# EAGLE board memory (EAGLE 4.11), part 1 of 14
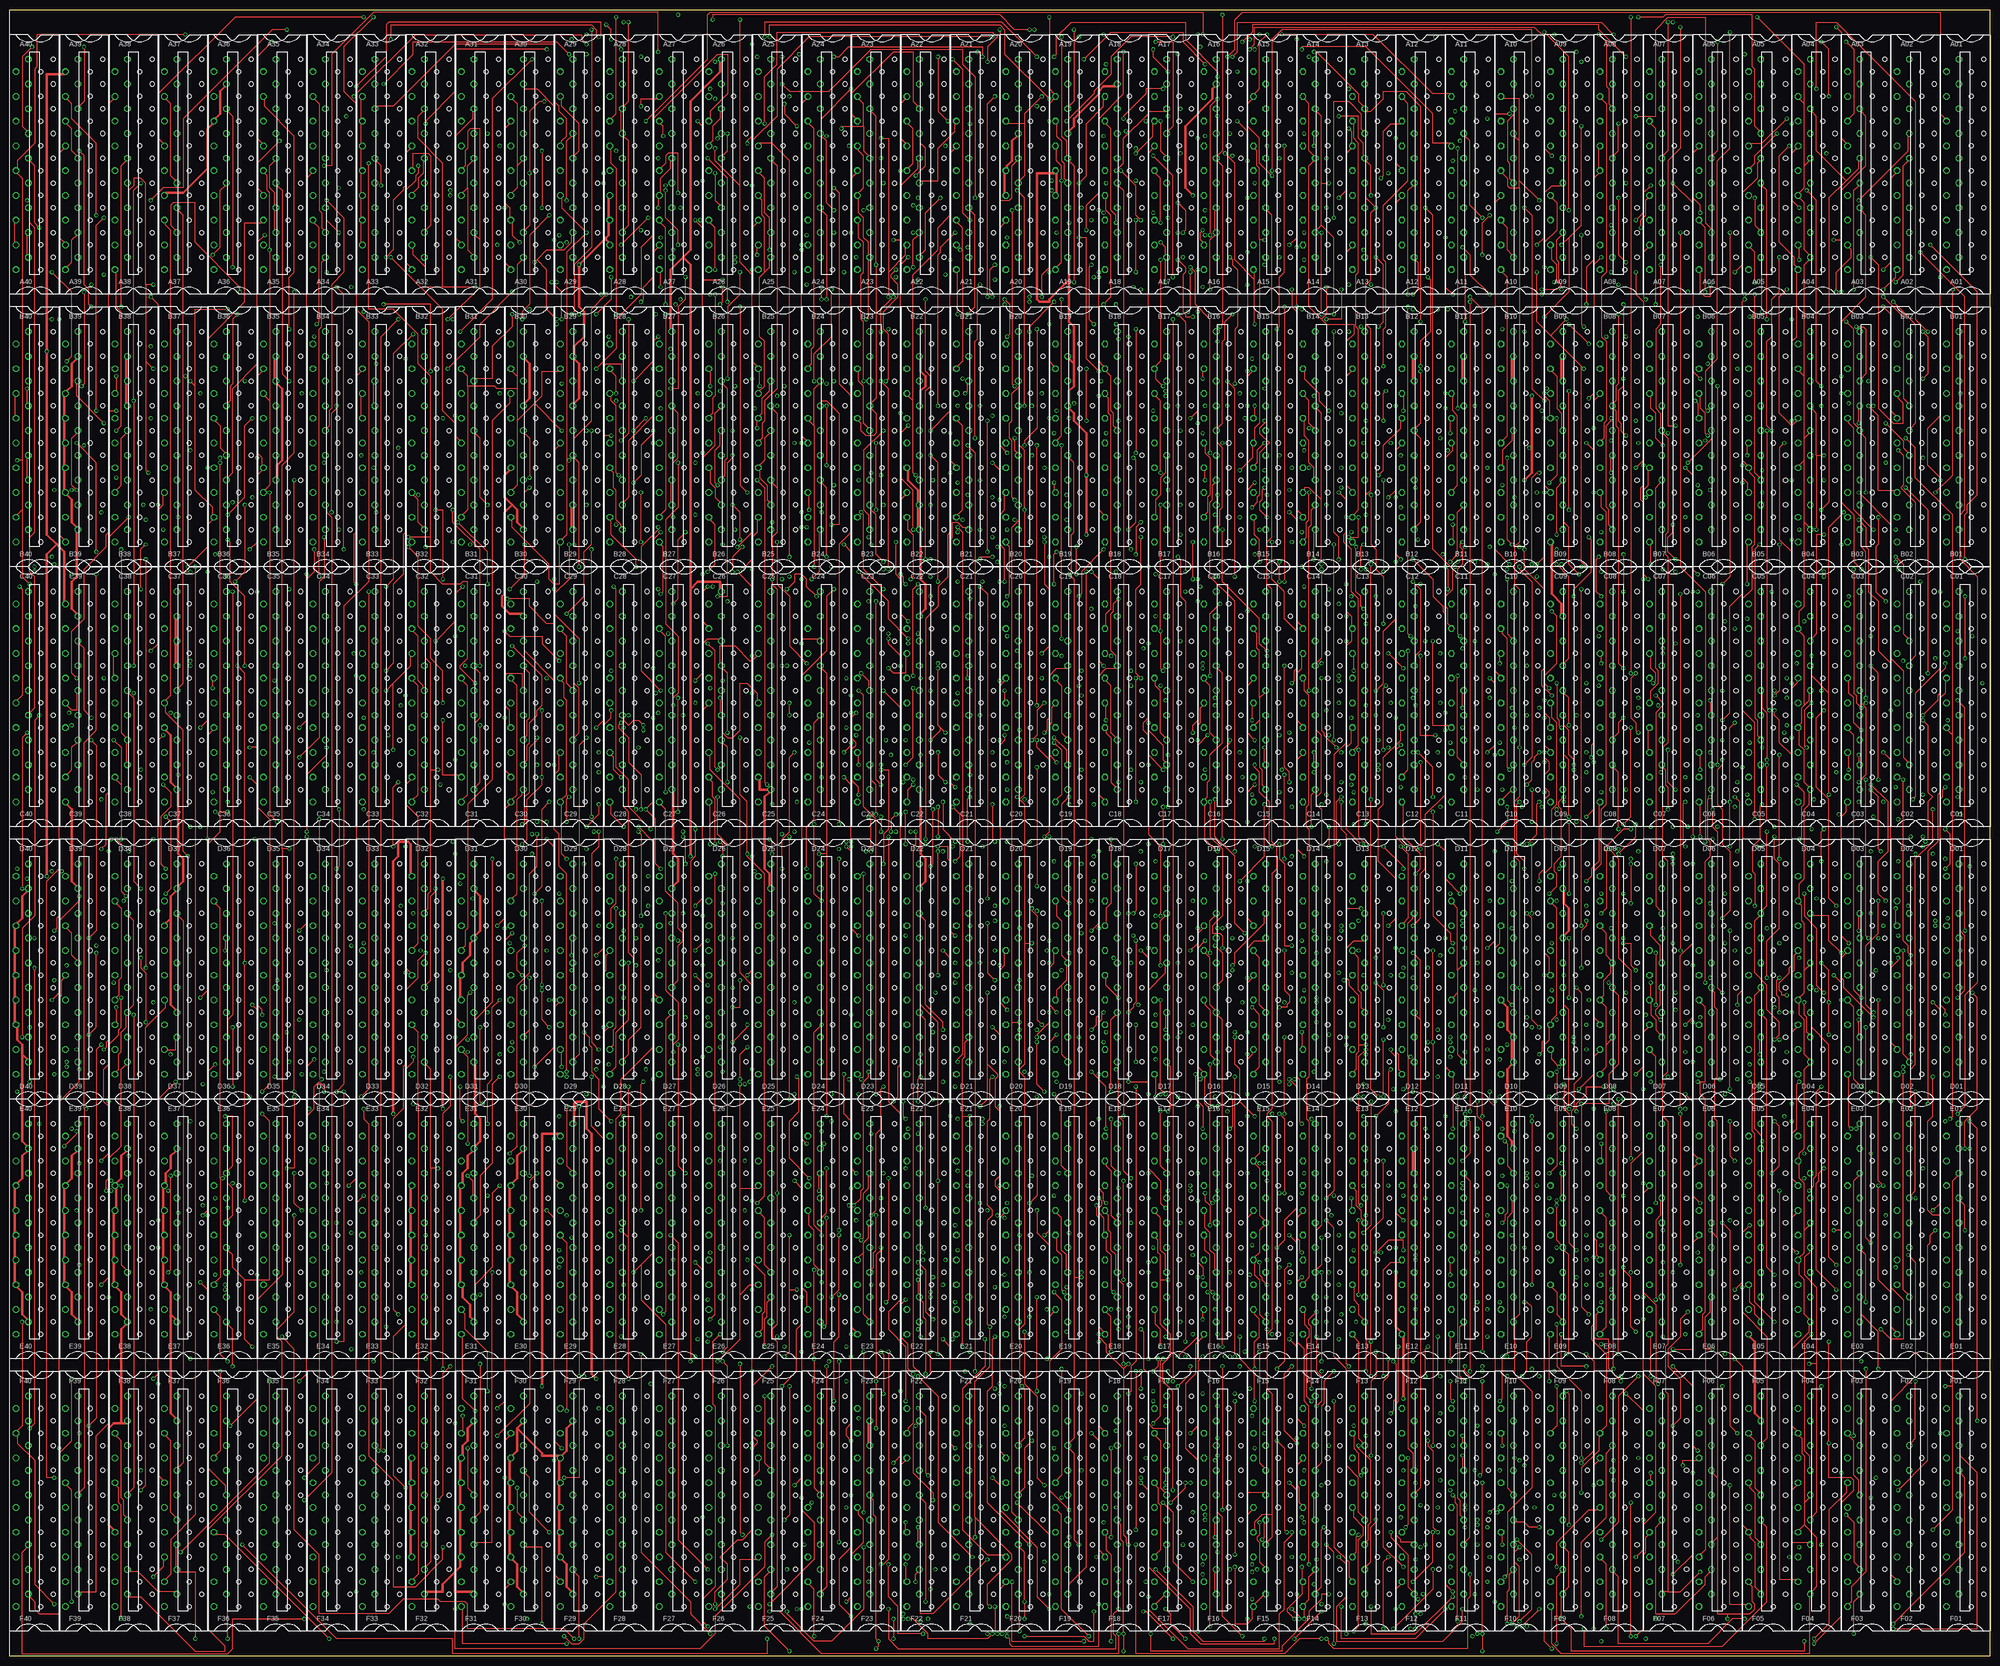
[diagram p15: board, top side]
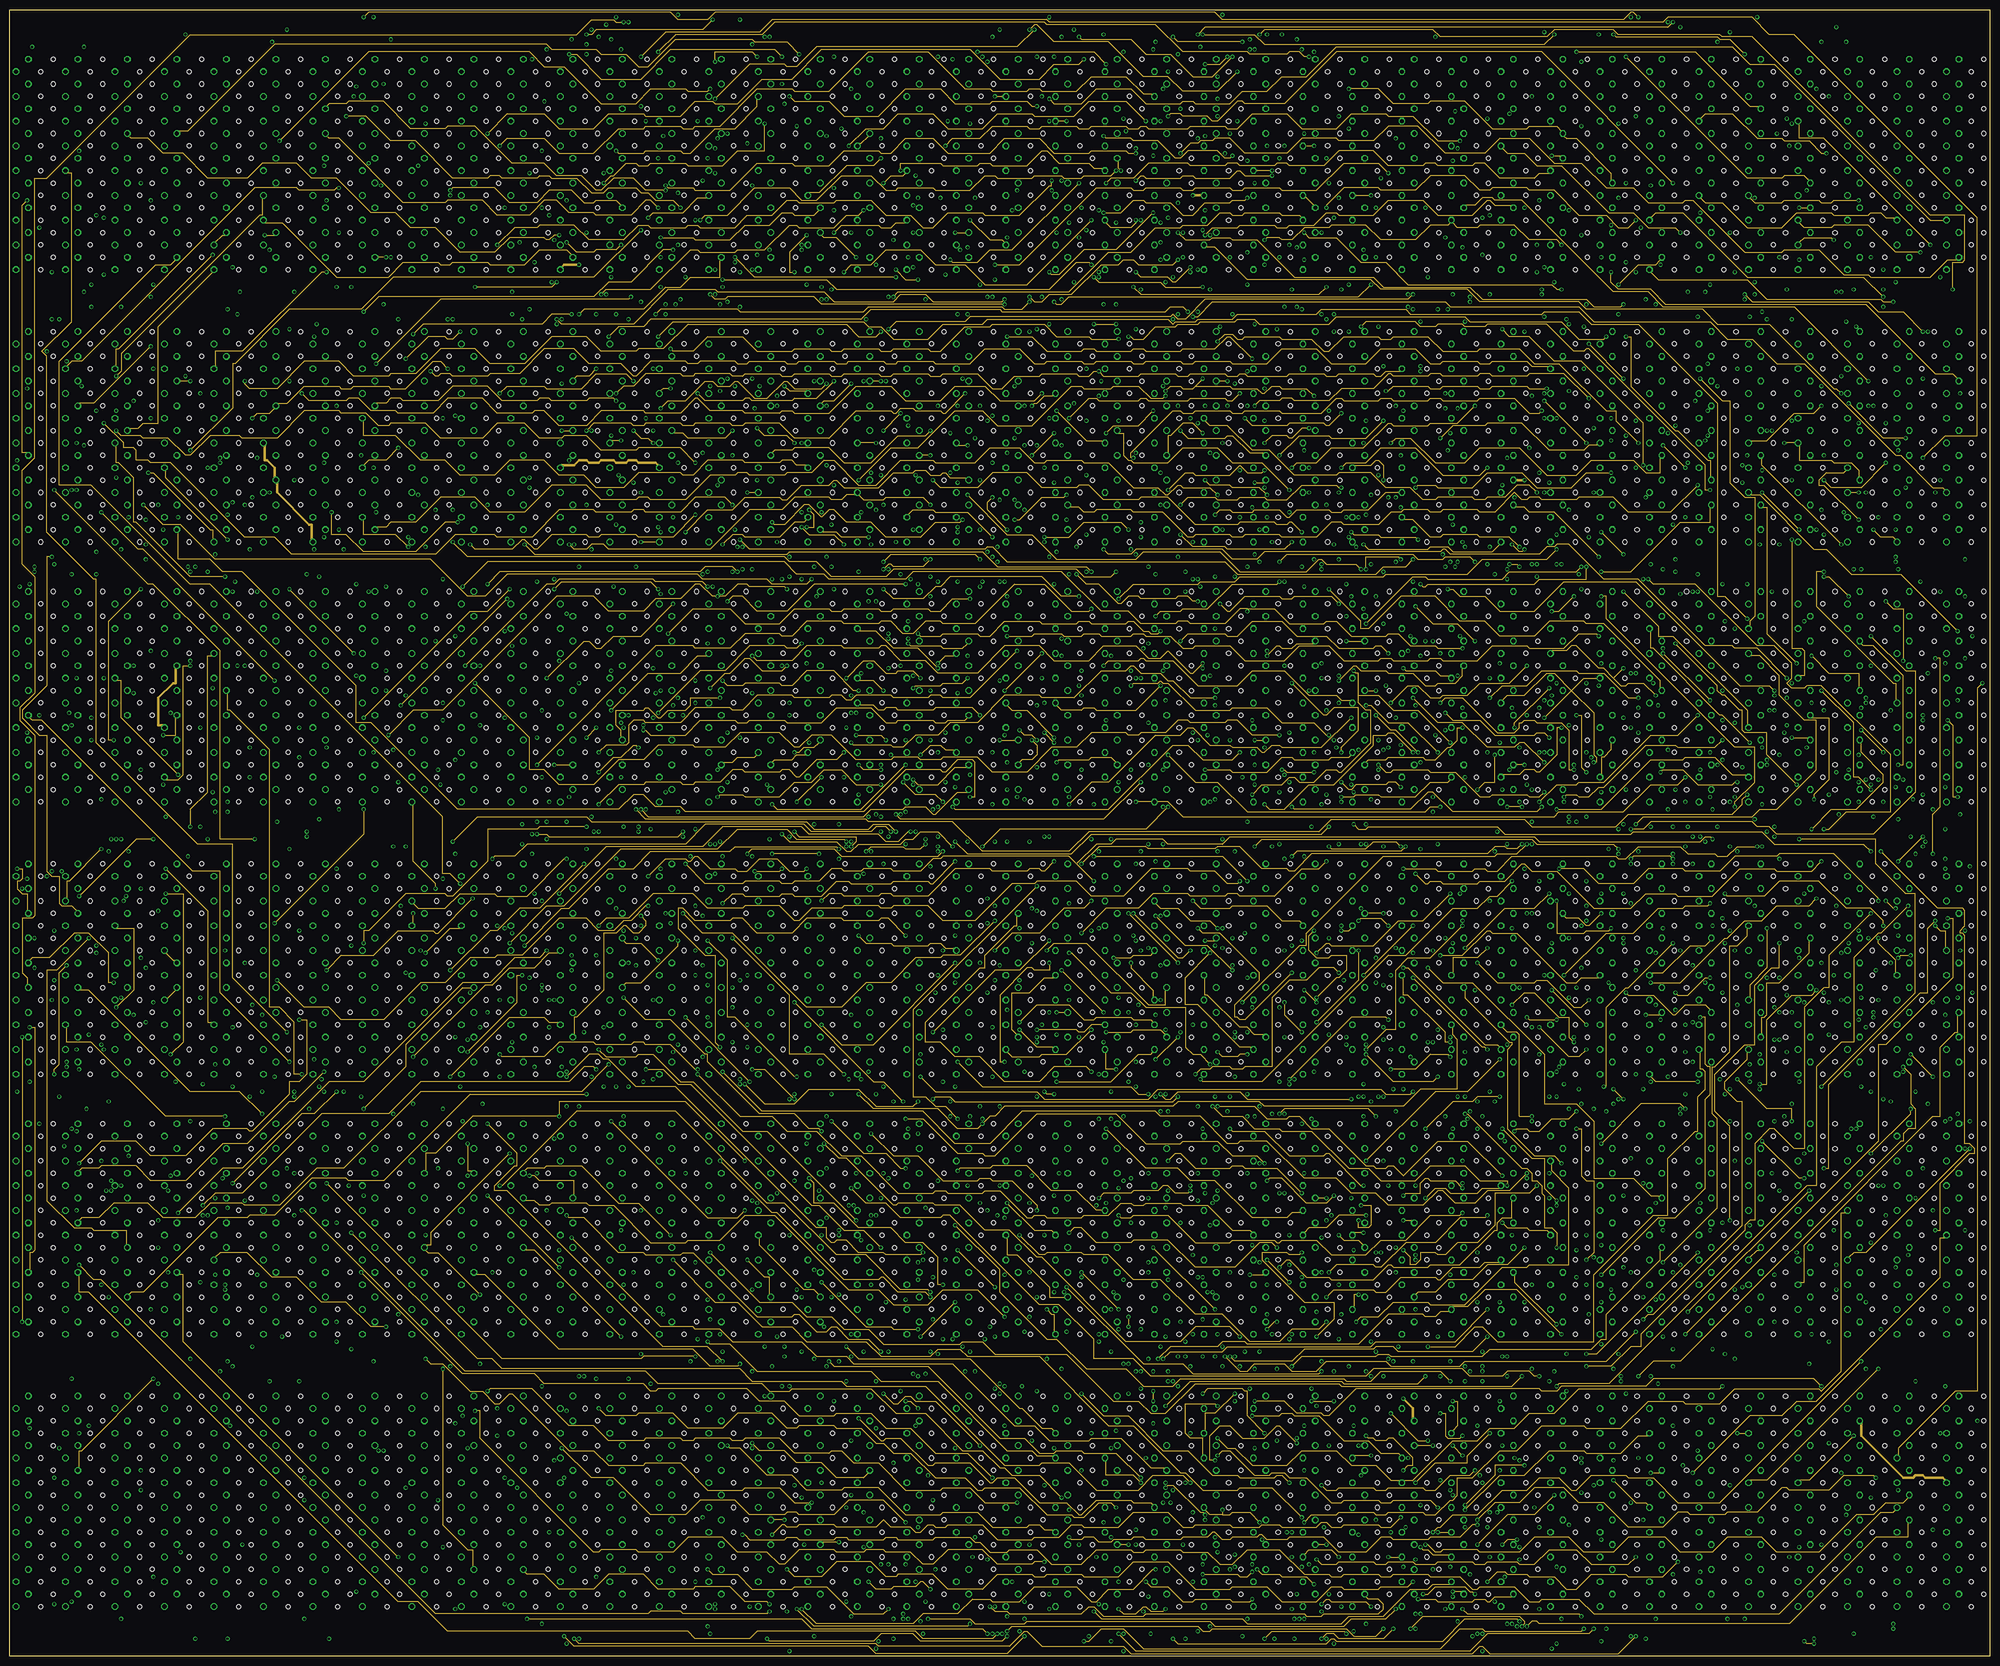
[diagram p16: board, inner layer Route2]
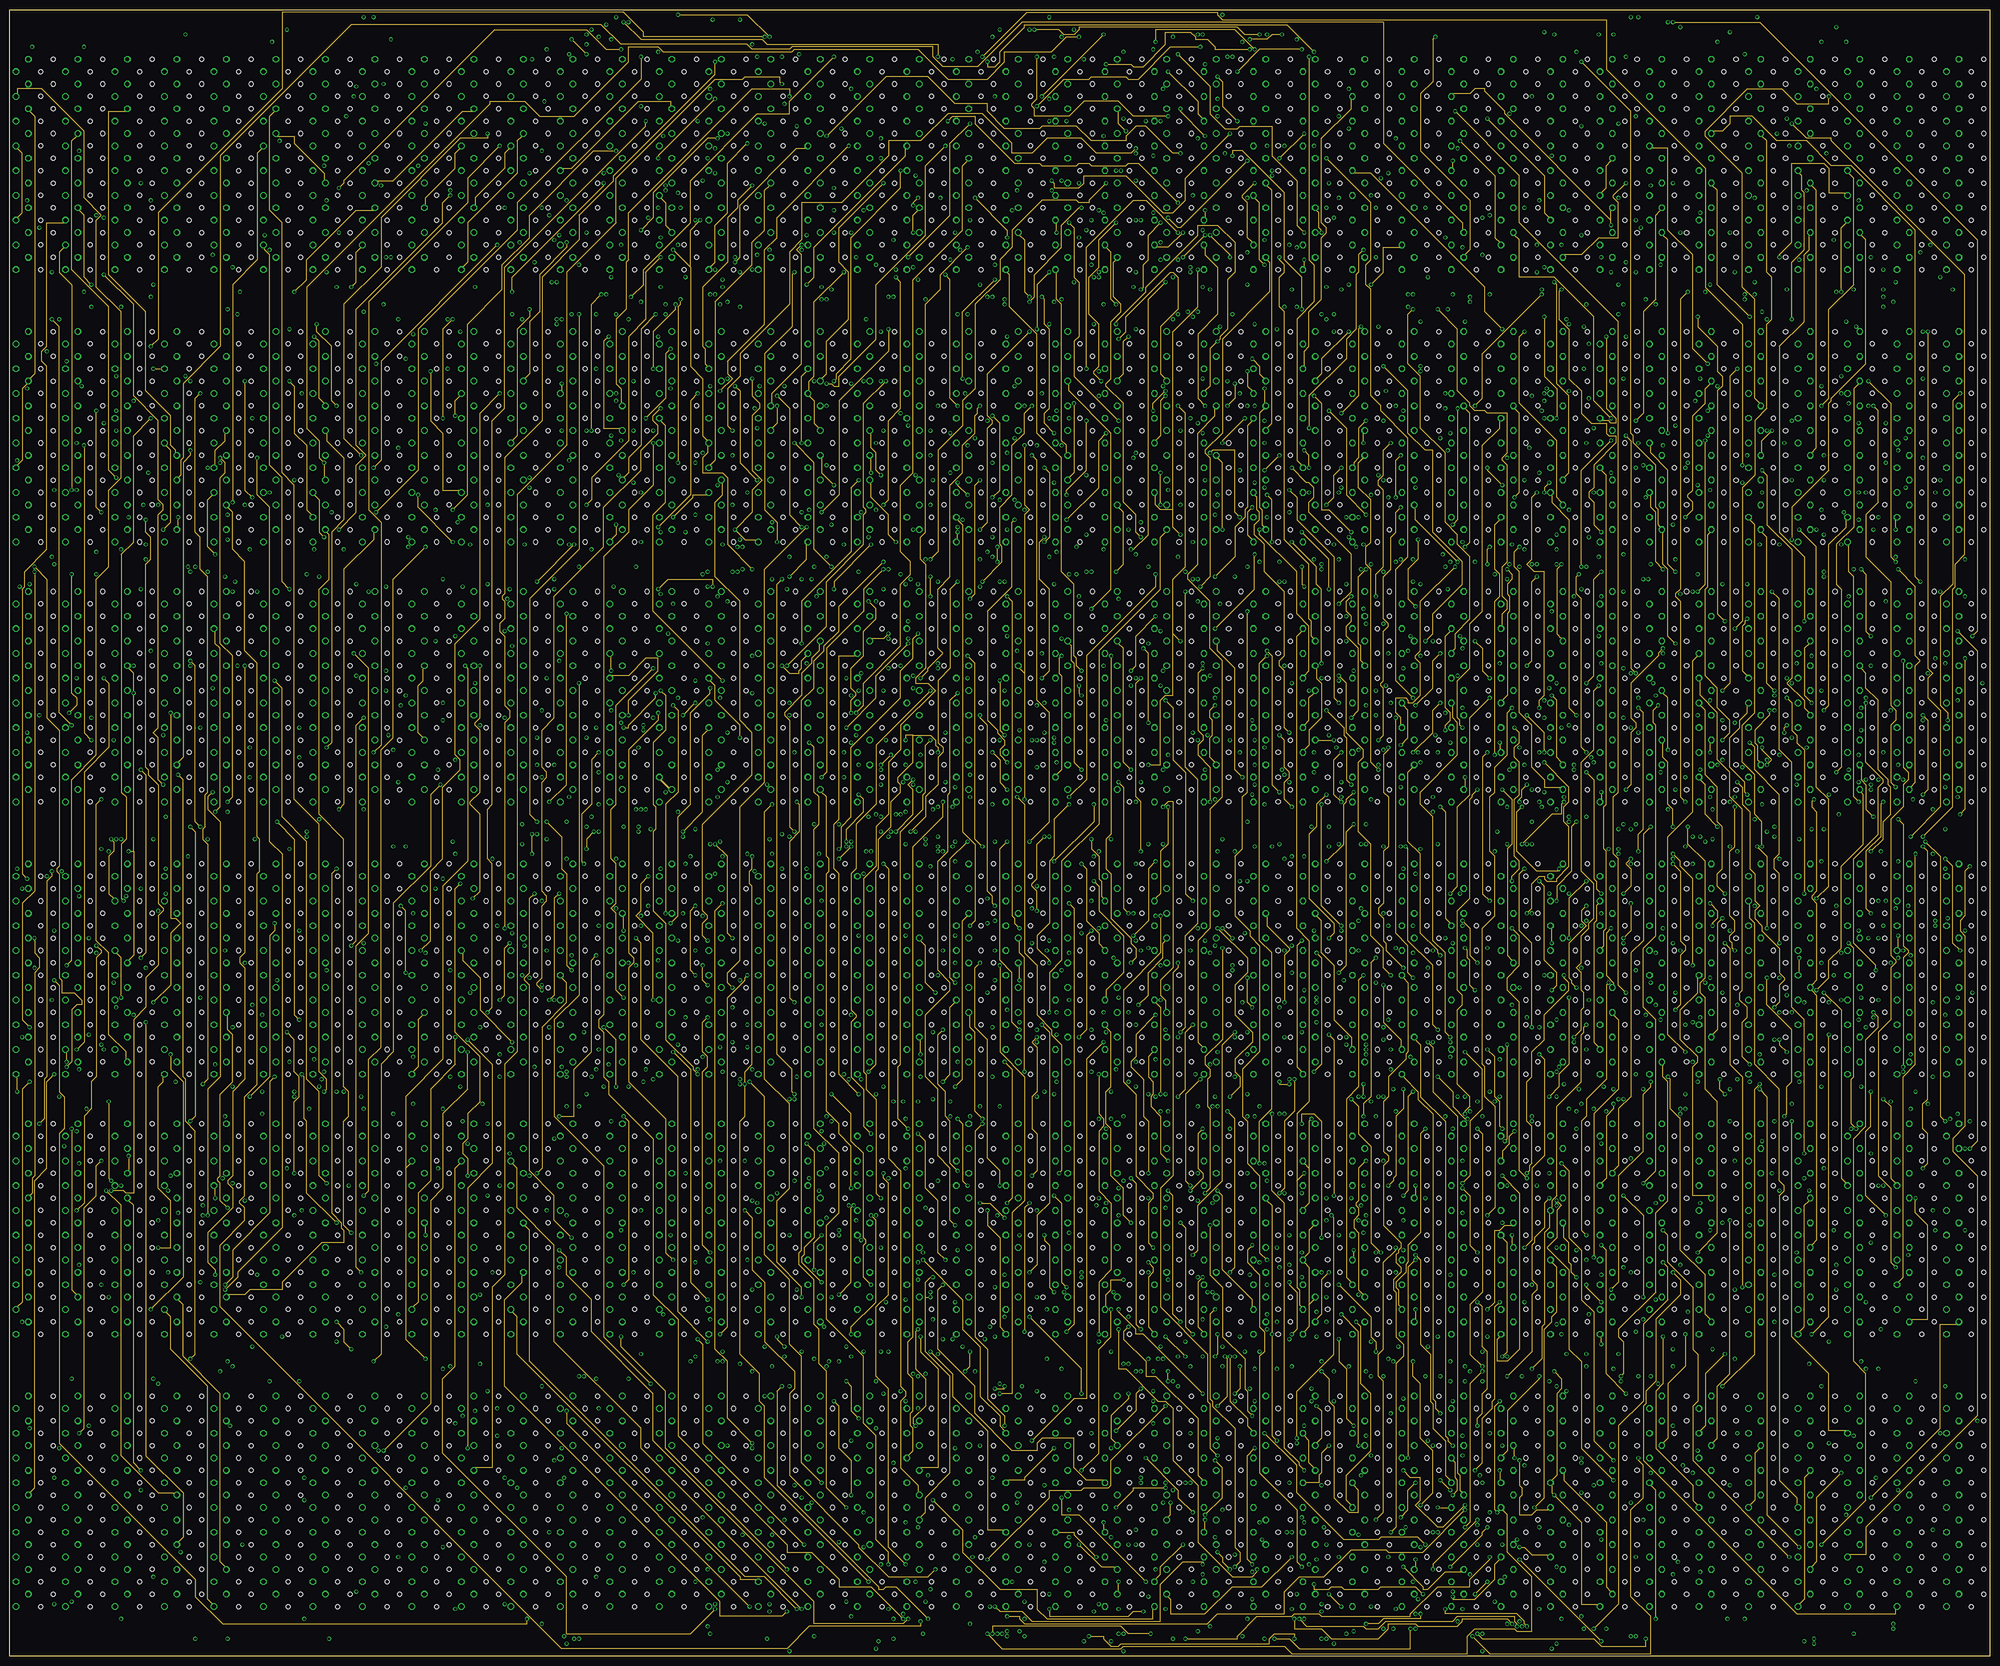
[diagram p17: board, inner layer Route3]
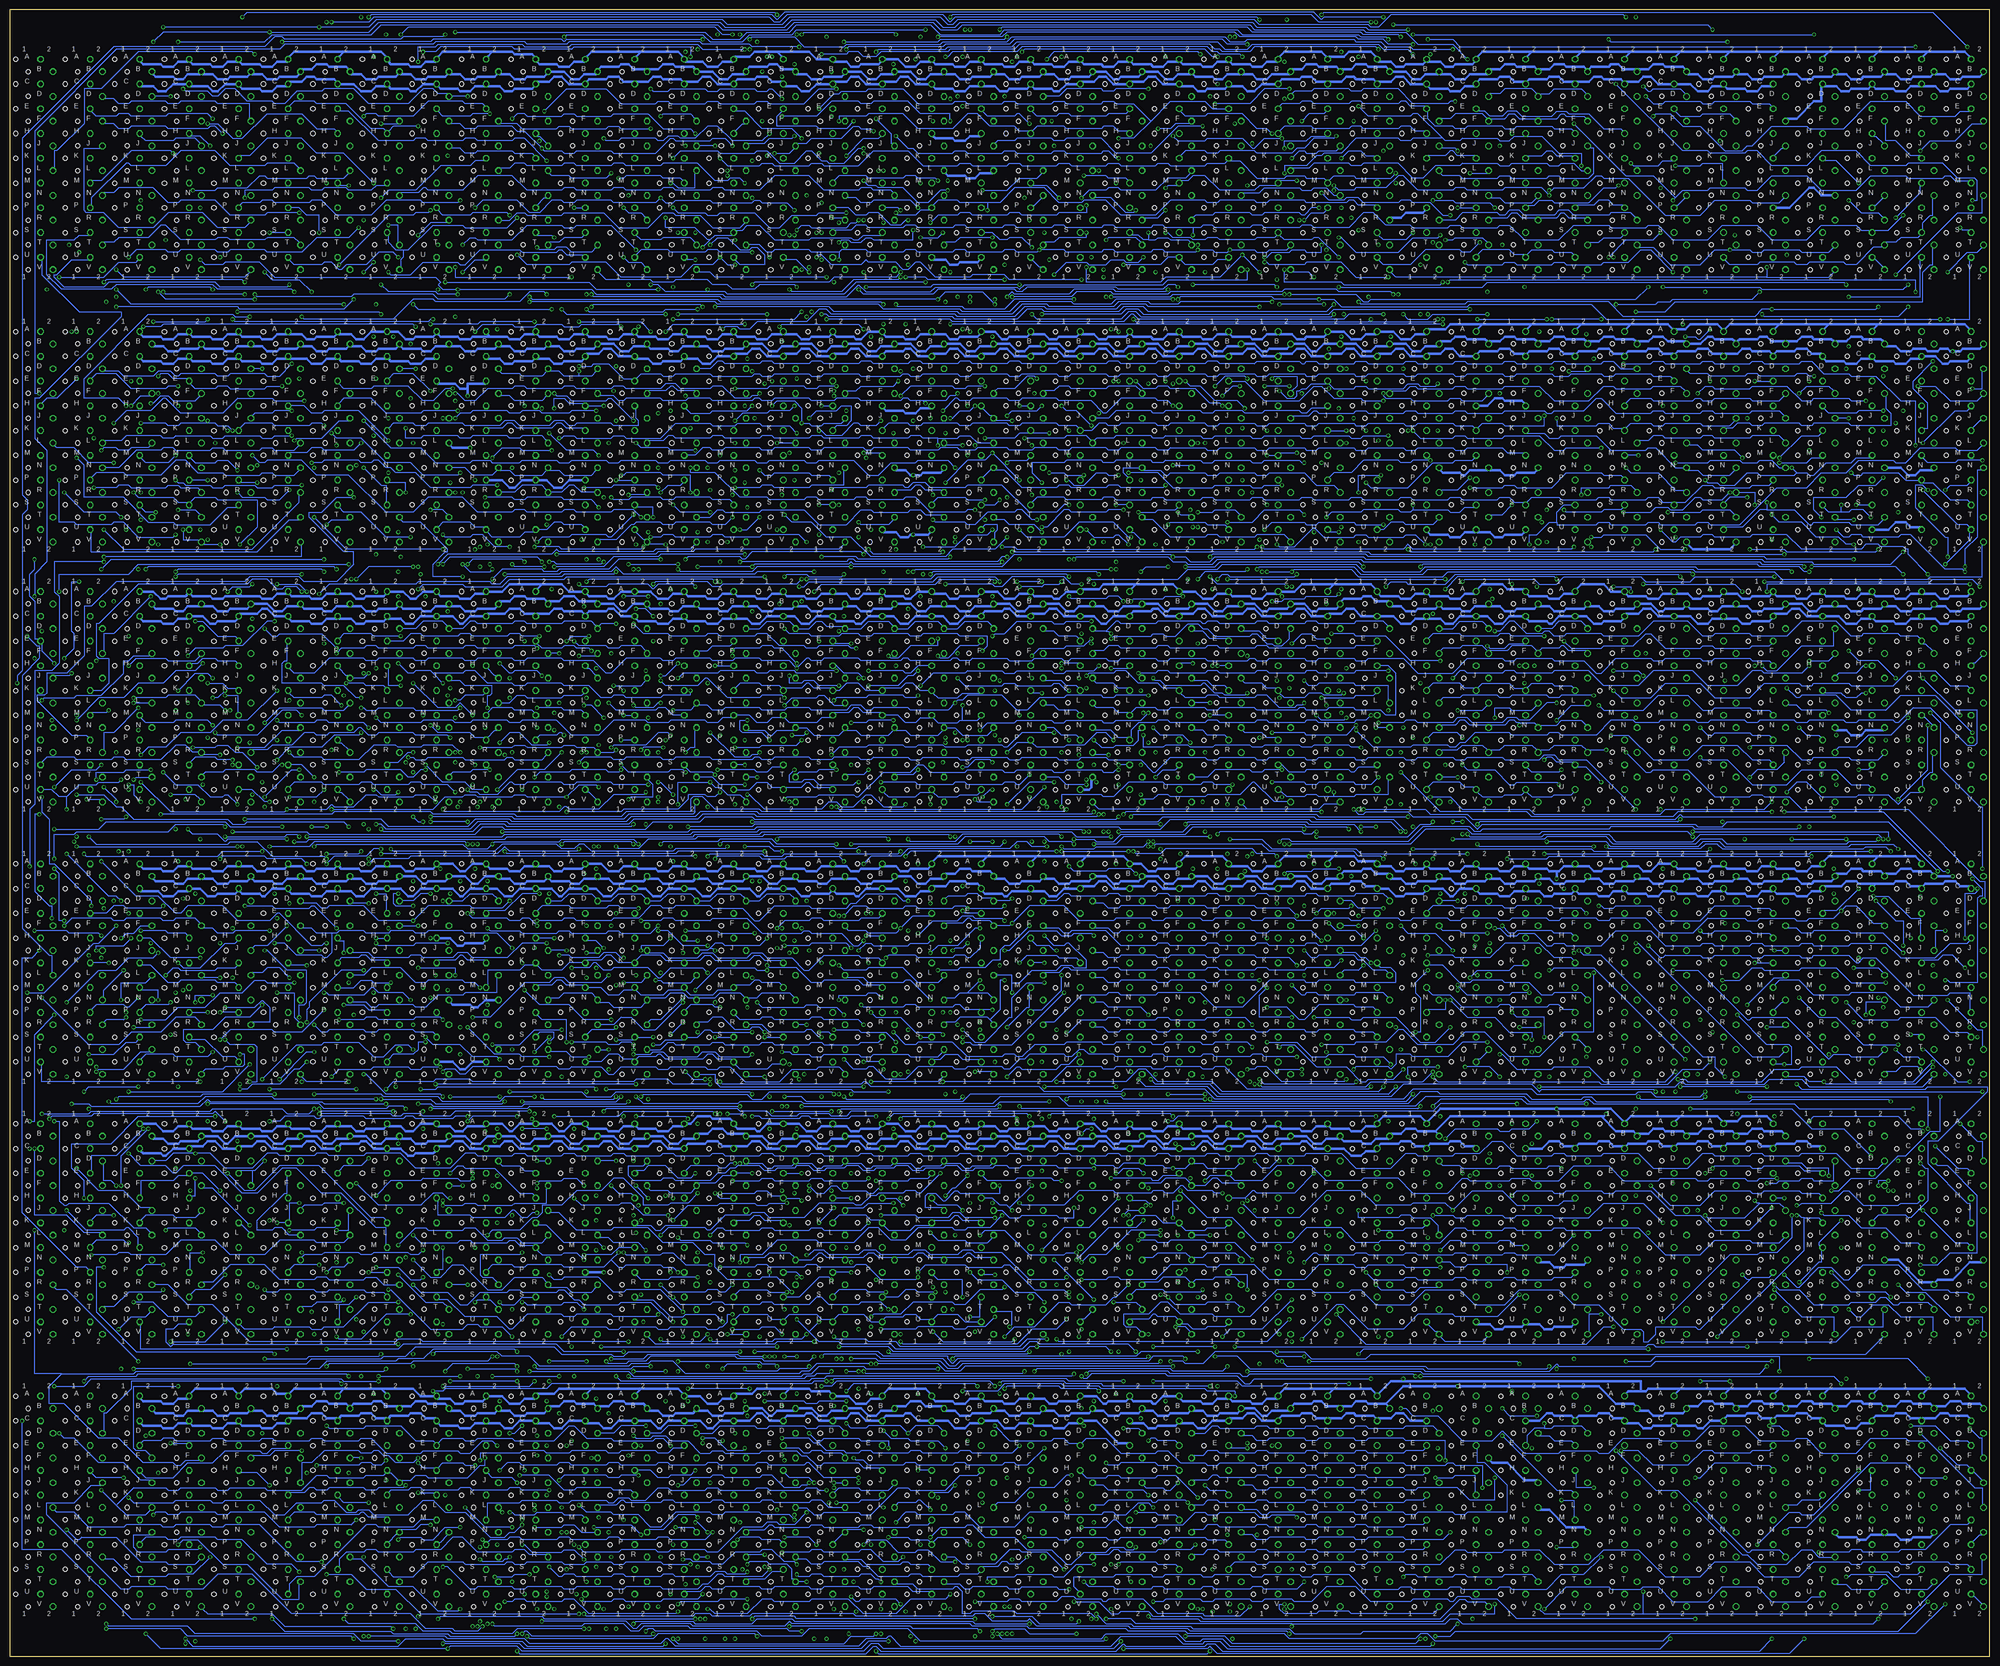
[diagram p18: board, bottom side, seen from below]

Size 508 x 422.28 mm. Coordinates in mm from the lower left corner, seen from the top.
Outline: 0,6.35 0,422.28 508,422.28 508,0 0,0 0,6.35
Copper layers (1*2*3*16): Top 0.035mm / dielectric 1.5mm / Route2 0.035mm / dielectric 0.15mm / Route3 0.035mm / dielectric 0.2mm / Bottom 0.035mm
Design rules "default": minimum track width 10mil, minimum drill 24mil, track to track 8mil, track to pad 8mil, pad to pad 8mil, via to via 8mil, smd to smd 8mil, copper to edge 10mil, drill to drill 8mil, minimum pad ring 10mil, minimum via ring 8mil, stop-mask expansion 4mil, vias tented up to drill 0mil, thermal gap 10mil
Net classes: 1 Supply: width 0.635 mm

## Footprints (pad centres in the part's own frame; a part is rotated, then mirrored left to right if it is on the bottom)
H807S = drill 1.092 octagon: A2 -1.587,28.575; B2 -4.763,25.4; C2 -1.587,22.225; D2 -4.763,19.05; E2 -1.587,15.875; F2 -4.763,12.7; H2 -1.587,9.525; J2 -4.763,6.35; K2 -1.587,3.175; L2 -4.763,0; M2 -1.587,-3.175; N2 -4.763,-6.35; P2 -1.587,-9.525; R2 -4.763,-12.7; S2 -1.587,-15.875; T2 -4.763,-19.05; U2 -1.587,-22.225; V2 -4.763,-25.4 | hole 1.092: 4.763,28.575; 1.587,25.4; 4.763,22.225; 1.587,19.05; 4.763,15.875; 1.587,12.7; 4.763,9.525; 1.587,6.35; 4.763,3.175; 1.587,0; 4.763,-3.175; 1.587,-6.35; 4.763,-9.525; 1.587,-12.7; 4.763,-15.875; 1.587,-19.05; 4.763,-22.225; 1.587,-25.4

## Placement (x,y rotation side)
A01  W023S  [H807S]  501.65,381 0 top
A02  W023S  [H807S]  488.95,381 0 top
A03  R001S  [H807S]  476.25,381 0 top
A04  R202S  [H807S]  463.55,381 0 top
A05  W050S  [H807S]  450.85,381 0 top
A06  W050S  [H807S]  438.15,381 0 top
A07  W050S  [H807S]  425.45,381 0 top
A08  R113S  [H807S]  412.75,381 0 top
A09  R107S  [H807S]  400.05,381 0 top
A10  R113S  [H807S]  387.35,381 0 top
A11  R111S  [H807S]  374.65,381 0 top
A12  R002S  [H807S]  361.95,381 0 top
A13  R002S  [H807S]  349.25,381 0 top
A14  R111S  [H807S]  336.55,381 0 top
A15  R113S  [H807S]  323.85,381 0 top
A16  R602S  [H807S]  311.15,381 0 top
A17  R107S  [H807S]  298.45,381 0 top
A18  R107S  [H807S]  285.75,381 0 top
A19  R603S  [H807S]  273.05,381 0 top
A20  R603S  [H807S]  260.35,381 0 top
A21  R111S  [H807S]  247.65,381 0 top
A22  R001S  [H807S]  234.95,381 0 top
A23  R111S  [H807S]  222.25,381 0 top
A24  R107S  [H807S]  209.55,381 0 top
A25  R111S  [H807S]  196.85,381 0 top
A26  R113S  [H807S]  184.15,381 0 top
A27  R113S  [H807S]  171.45,381 0 top
A28  R602S  [H807S]  158.75,381 0 top
A29  R202S  [H807S]  146.05,381 0 top
A30  R202S  [H807S]  133.35,381 0 top
A31  R202S  [H807S]  120.65,381 0 top
A32  R202S  [H807S]  107.95,381 0 top
A33  R001S  [H807S]  95.25,381 0 top
A34  R111S  [H807S]  82.55,381 0 top
A35  R001S  [H807S]  69.85,381 0 top
A36  R302S  [H807S]  57.15,381 0 top
A37  R602S  [H807S]  44.45,381 0 top
A38  R111S  [H807S]  31.75,381 0 top
A39  R002S  [H807S]  19.05,381 0 top
A40  R107S  [H807S]  6.35,381 0 top
B01  W023S  [H807S]  501.65,311.15 0 top
B02  W023S  [H807S]  488.95,311.15 0 top
B03  W050S  [H807S]  476.25,311.15 0 top
B04  R202S  [H807S]  463.55,311.15 0 top
B05  W005S  [H807S]  450.85,311.15 0 top
B06  W050S  [H807S]  438.15,311.15 0 top
B07  W050S  [H807S]  425.45,311.15 0 top
B08  R107S  [H807S]  412.75,311.15 0 top
B09  R202S  [H807S]  400.05,311.15 0 top
B10  R202S  [H807S]  387.35,311.15 0 top
B11  R202S  [H807S]  374.65,311.15 0 top
B12  R202S  [H807S]  361.95,311.15 0 top
B13  R111S  [H807S]  349.25,311.15 0 top
B14  R002S  [H807S]  336.55,311.15 0 top
B15  R113S  [H807S]  323.85,311.15 0 top
B16  R107S  [H807S]  311.15,311.15 0 top
B17  R113S  [H807S]  298.45,311.15 0 top
B18  R603S  [H807S]  285.75,311.15 0 top
B19  R603S  [H807S]  273.05,311.15 0 top
B20  R111S  [H807S]  260.35,311.15 0 top
B21  R002S  [H807S]  247.65,311.15 0 top
B22  R603S  [H807S]  234.95,311.15 0 top
B23  R111S  [H807S]  222.25,311.15 0 top
B24  R113S  [H807S]  209.55,311.15 0 top
B25  R113S  [H807S]  196.85,311.15 0 top
B26  R002S  [H807S]  184.15,311.15 0 top
B27  R602S  [H807S]  171.45,311.15 0 top
B28  R202S  [H807S]  158.75,311.15 0 top
B29  R603S  [H807S]  146.05,311.15 0 top
B30  R603S  [H807S]  133.35,311.15 0 top
B31  R603S  [H807S]  120.65,311.15 0 top
B32  R401S  [H807S]  107.95,311.15 0 top
B33  R107S  [H807S]  95.25,311.15 0 top
B34  R202S  [H807S]  82.55,311.15 0 top
B35  R202S  [H807S]  69.85,311.15 0 top
B36  R113S  [H807S]  57.15,311.15 0 top
B37  R107S  [H807S]  44.45,311.15 0 top
B38  R603S  [H807S]  31.75,311.15 0 top
B39  W028S  [H807S]  19.05,311.15 0 top
B40  W005S  [H807S]  6.35,311.15 0 top
C01  W023S  [H807S]  501.65,244.47 0 top
C02  W023S  [H807S]  488.95,244.47 0 top
C03  W050S  [H807S]  476.25,244.47 0 top
C04  R202S  [H807S]  463.55,244.47 0 top
C05  R107S  [H807S]  450.85,244.47 0 top
C06  W050S  [H807S]  438.15,244.47 0 top
C07  R111S  [H807S]  425.45,244.47 0 top
C08  R002S  [H807S]  412.75,244.47 0 top
C09  R107S  [H807S]  400.05,244.47 0 top
C10  R111S  [H807S]  387.35,244.47 0 top
C11  R001S  [H807S]  374.65,244.47 0 top
C12  R111S  [H807S]  361.95,244.47 0 top
C13  R107S  [H807S]  349.25,244.47 0 top
C14  R113S  [H807S]  336.55,244.47 0 top
C15  R202S  [H807S]  323.85,244.47 0 top
C16  R202S  [H807S]  311.15,244.47 0 top
C17  R202S  [H807S]  298.45,244.47 0 top
C18  R202S  [H807S]  285.75,244.47 0 top
C19  R202S  [H807S]  273.05,244.47 0 top
C20  R202S  [H807S]  260.35,244.47 0 top
C21  R107S  [H807S]  247.65,244.47 0 top
C22  M517S  [H807S]  234.95,244.47 0 top
C23  W512S  [H807S]  222.25,244.47 0 top
C24  R107S  [H807S]  209.55,244.47 0 top
C25  M517S  [H807S]  196.85,244.47 0 top
C26  W512S  [H807S]  184.15,244.47 0 top
C27  M517S  [H807S]  171.45,244.47 0 top
C28  W023S  [H807S]  158.75,244.47 0 top
C29  R202S  [H807S]  146.05,244.47 0 top
C30  R202S  [H807S]  133.35,244.47 0 top
C31  R202S  [H807S]  120.65,244.47 0 top
C32  R202S  [H807S]  107.95,244.47 0 top
C33  EMPTYS  [H807S]  95.25,244.47 0 top
C34  EMPTYS  [H807S]  82.55,244.47 0 top
C35  EMPTYS  [H807S]  69.85,244.47 0 top
C36  R107S  [H807S]  57.15,244.47 0 top
C37  R603S  [H807S]  44.45,244.47 0 top
C38  R602S  [H807S]  31.75,244.47 0 top
C39  W501S  [H807S]  19.05,244.47 0 top
C40  W506S  [H807S]  6.35,244.47 0 top
D01  W023S  [H807S]  501.65,174.62 0 top
D02  W023S  [H807S]  488.95,174.62 0 top
D03  W050S  [H807S]  476.25,174.62 0 top
D04  R202S  [H807S]  463.55,174.62 0 top
D05  R107S  [H807S]  450.85,174.62 0 top
D06  R113S  [H807S]  438.15,174.62 0 top
D07  R113S  [H807S]  425.45,174.62 0 top
D08  R113S  [H807S]  412.75,174.62 0 top
D09  R603S  [H807S]  400.05,174.62 0 top
D10  R603S  [H807S]  387.35,174.62 0 top
D11  R202S  [H807S]  374.65,174.62 0 top
D12  R202S  [H807S]  361.95,174.62 0 top
D13  R202S  [H807S]  349.25,174.62 0 top
D14  R202S  [H807S]  336.55,174.62 0 top
D15  R202S  [H807S]  323.85,174.62 0 top
D16  R202S  [H807S]  311.15,174.62 0 top
D17  R151S  [H807S]  298.45,174.62 0 top
D18  R107S  [H807S]  285.75,174.62 0 top
D19  R202S  [H807S]  273.05,174.62 0 top
D20  R202S  [H807S]  260.35,174.62 0 top
D21  M507S  [H807S]  247.65,174.62 0 top
D22  M507S  [H807S]  234.95,174.62 0 top
D23  EMPTYS  [H807S]  222.25,174.62 0 top
D24  EMPTYS  [H807S]  209.55,174.62 0 top
D25  EMPTYS  [H807S]  196.85,174.62 0 top
D26  EMPTYS  [H807S]  184.15,174.62 0 top
D27  M507S  [H807S]  171.45,174.62 0 top
D28  W023S  [H807S]  158.75,174.62 0 top
D29  R107S  [H807S]  146.05,174.62 0 top
D30  R401S  [H807S]  133.35,174.62 0 top
D31  R603S  [H807S]  120.65,174.62 0 top
D32  R113S  [H807S]  107.95,174.62 0 top
D33  EMPTYS  [H807S]  95.25,174.62 0 top
D34  EMPTYS  [H807S]  82.55,174.62 0 top
D35  EMPTYS  [H807S]  69.85,174.62 0 top
D36  R111S  [H807S]  57.15,174.62 0 top
D37  R302S  [H807S]  44.45,174.62 0 top
D38  R202S  [H807S]  31.75,174.62 0 top
D39  R002S  [H807S]  19.05,174.62 0 top
D40  W028S  [H807S]  6.35,174.62 0 top
E01  W023S  [H807S]  501.65,107.95 0 top
E02  W023S  [H807S]  488.95,107.95 0 top
E03  R001S  [H807S]  476.25,107.95 0 top
E04  R202S  [H807S]  463.55,107.95 0 top
E05  W501S  [H807S]  450.85,107.95 0 top
E06  R202S  [H807S]  438.15,107.95 0 top
E07  W050S  [H807S]  425.45,107.95 0 top
E08  W005S  [H807S]  412.75,107.95 0 top
E09  R113S  [H807S]  400.05,107.95 0 top
E10  R113S  [H807S]  387.35,107.95 0 top
E11  R113S  [H807S]  374.65,107.95 0 top
E12  R202S  [H807S]  361.95,107.95 0 top
E13  R113S  [H807S]  349.25,107.95 0 top
E14  R113S  [H807S]  336.55,107.95 0 top
E15  R202S  [H807S]  323.85,107.95 0 top
E16  R202S  [H807S]  311.15,107.95 0 top
E17  R202S  [H807S]  298.45,107.95 0 top
E18  R202S  [H807S]  285.75,107.95 0 top
E19  R202S  [H807S]  273.05,107.95 0 top
E20  R202S  [H807S]  260.35,107.95 0 top
E21  EMPTYS  [H807S]  247.65,107.95 0 top
E22  R401S  [H807S]  234.95,107.95 0 top
E23  R202S  [H807S]  222.25,107.95 0 top
E24  R202S  [H807S]  209.55,107.95 0 top
E25  R202S  [H807S]  196.85,107.95 0 top
E26  EMPTYS  [H807S]  184.15,107.95 0 top
E27  EMPTYS  [H807S]  171.45,107.95 0 top
E28  EMPTYS  [H807S]  158.75,107.95 0 top
E29  R111S  [H807S]  146.05,107.95 0 top
E30  W021S  [H807S]  133.35,107.95 0 top
E31  W021S  [H807S]  120.65,107.95 0 top
E32  W021S  [H807S]  107.95,107.95 0 top
E33  EMPTYS  [H807S]  95.25,107.95 0 top
E34  EMPTYS  [H807S]  82.55,107.95 0 top
E35  EMPTYS  [H807S]  69.85,107.95 0 top
E36  R113S  [H807S]  57.15,107.95 0 top
E37  W028S  [H807S]  44.45,107.95 0 top
E38  W028S  [H807S]  31.75,107.95 0 top
E39  W028S  [H807S]  19.05,107.95 0 top
E40  W028S  [H807S]  6.35,107.95 0 top
F01  W023S  [H807S]  501.65,38.1 0 top
F02  W023S  [H807S]  488.95,38.1 0 top
F03  R202S  [H807S]  476.25,38.1 0 top
F04  R202S  [H807S]  463.55,38.1 0 top
F05  R202S  [H807S]  450.85,38.1 0 top
F06  R001S  [H807S]  438.15,38.1 0 top
F07  R111S  [H807S]  425.45,38.1 0 top
F08  R111S  [H807S]  412.75,38.1 0 top
F09  R111S  [H807S]  400.05,38.1 0 top
F10  R107S  [H807S]  387.35,38.1 0 top
F11  R107S  [H807S]  374.65,38.1 0 top
F12  R107S  [H807S]  361.95,38.1 0 top
F13  R107S  [H807S]  349.25,38.1 0 top
F14  R113S  [H807S]  336.55,38.1 0 top
F15  R111S  [H807S]  323.85,38.1 0 top
F16  R001S  [H807S]  311.15,38.1 0 top
F17  R111S  [H807S]  298.45,38.1 0 top
F18  R107S  [H807S]  285.75,38.1 0 top
F19  R107S  [H807S]  273.05,38.1 0 top
F20  R107S  [H807S]  260.35,38.1 0 top
F21  EMPTYS  [H807S]  247.65,38.1 0 top
F22  W005S  [H807S]  234.95,38.1 0 top
F23  R202S  [H807S]  222.25,38.1 0 top
F24  R107S  [H807S]  209.55,38.1 0 top
F25  R107S  [H807S]  196.85,38.1 0 top
F26  EMPTYS  [H807S]  184.15,38.1 0 top
F27  EMPTYS  [H807S]  171.45,38.1 0 top
F28  EMPTYS  [H807S]  158.75,38.1 0 top
F29  W021S  [H807S]  146.05,38.1 0 top
F30  W021S  [H807S]  133.35,38.1 0 top
F31  W021S  [H807S]  120.65,38.1 0 top
F32  W021S  [H807S]  107.95,38.1 0 top
F33  EMPTYS  [H807S]  95.25,38.1 0 top
F34  EMPTYS  [H807S]  82.55,38.1 0 top
F35  EMPTYS  [H807S]  69.85,38.1 0 top
F36  R113S  [H807S]  57.15,38.1 0 top
F37  R602S  [H807S]  44.45,38.1 0 top
F38  R602S  [H807S]  31.75,38.1 0 top
F39  R602S  [H807S]  19.05,38.1 0 top
F40  R111S  [H807S]  6.35,38.1 0 top

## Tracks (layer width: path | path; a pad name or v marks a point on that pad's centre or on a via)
(ISZ*ZI)+JMS+(OP+IOT)*SKP
  Top 0.254: 323.85,36.2 321.31,36.2 319.4,34.29 319.4,32.38 F15.N2 | 323.85,36.2 323.85,30.48 322.58,29.21 F15.P2 | 323.85,36.2 323.85,67.31 322.58,68.58 322.58,82.55 323.85,83.82 323.85,137.16 322.58,138.43 322.58,139.06 323.85,140.34 323.85,200.66 325.12,201.93 325.12,207.64 323.85,208.91 323.85,273.69 322.58,274.96 322.58,285.75 323.85,287.02 323.85,369.57 322.58,370.84 A15.P2
  Bottom 0.254: F19.M2 271.78,34.29 272.42,33.66 276.86,33.66 277.5,33.02 286.38,33.02 287.02,33.66 289.56,33.66 290.19,33.02 299.08,33.02 299.72,33.66 302.26,33.66 302.89,33.02 311.79,33.02 312.42,33.66 313.06,33.66 314.32,32.38 318.77,32.38 F15.N2
(LAS+DEPS+EXS)  (via drill 0.61)
  Top 0.254: v250.82,283.21 v250.82,316.87
  Route3 0.254: v52.7,282.58 50.8,284.48 50.8,296.55 52.07,297.81 B36.R2
  Bottom 0.254: v52.7,282.58 158.75,282.58 159.38,283.21 v250.82,283.21 | v250.82,316.87 255.27,316.87 B20.J2 255.91,318.14 256.54,318.14 258.44,320.04 B20.H2
-15V  (via drill 0.61)
  Top 0.635: 12.06,285.12 9.53,287.66 v9.53,334.65 9.53,405.77 13.97,405.77 A39.B2 | 12.06,285.12 13.97,283.21 13.97,270.51 C39.B2 | v136.53,69.22 136.53,133.99 140.97,133.99 E29.B2 | v98.42,139.06 98.42,203.84 99.69,205.1 99.69,208.91 102.23,208.91 102.87,208.28 102.87,200.66 D32.B2 | 12.06,285.12 9.53,282.58 v9.53,200.03
  Bottom 0.635: A40.B2 1.91,405.77 2.54,405.13 6.99,405.13 7.62,404.5 10.16,404.5 11.43,405.77 13.97,405.77 A39.B2 14.61,405.77 15.24,405.13 19.68,405.13 20.32,404.5 22.86,404.5 24.13,405.77 26.67,405.77 A38.B2 27.3,405.77 27.94,405.13 32.38,405.13 33.02,404.5 35.56,404.5 36.83,405.77 39.37,405.77 A37.B2 40.01,405.77 40.64,405.13 45.09,405.13 45.72,404.5 48.26,404.5 49.53,405.77 52.07,405.77 A36.B2 52.7,405.77 53.34,405.13 57.78,405.13 58.42,404.5 60.96,404.5 62.23,405.77 64.77,405.77 A35.B2 65.41,405.77 66.04,405.13 70.48,405.13 71.12,404.5 73.66,404.5 74.93,405.77 77.47,405.77 A34.B2 78.11,407.04 78.74,407.67 83.19,407.67 83.82,408.31 86.36,408.31 87.63,407.04 90.17,407.04 A33.B2 90.81,407.04 93.98,407.04 95.25,408.31 97.16,408.31 97.79,407.67 102.23,407.67 102.87,407.04 A32.B2 103.5,407.04 104.14,407.67 108.58,407.67 109.22,408.31 111.76,408.31 113.03,407.04 115.57,407.04 A31.B2 116.2,407.04 116.84,407.67 121.28,407.67 121.92,408.31 124.46,408.31 125.73,407.04 128.27,407.04 A30.B2 128.91,405.77 133.35,405.77 134.62,404.5 137.16,404.5 138.43,405.77 140.97,405.77 A29.B2 141.6,405.77 144.78,405.77 146.05,404.5 147.96,404.5 149.86,406.4 153.67,406.4 A28.B2 154.31,407.04 154.94,407.67 159.38,407.67 160.02,408.31 162.56,408.31 163.83,407.04 166.37,407.04 A27.B2 167,407.04 167.64,407.67 172.09,407.67 172.72,408.31 175.26,408.31 176.53,407.04 179.07,407.04 A26.B2 179.71,405.77 184.15,405.77 185.42,404.5 187.96,404.5 189.23,405.77 191.77,405.77 A25.B2 192.41,405.77 195.58,405.77 196.85,404.5 198.75,404.5 199.39,405.13 203.84,405.13 204.47,405.77 A24.B2 205.1,405.77 208.28,405.77 209.55,404.5 211.46,404.5 213.36,406.4 217.17,406.4 A23.B2 217.81,405.77 218.44,405.13 222.88,405.13 223.52,404.5 224.79,404.5 226.69,406.4 229.87,406.4 A22.B2 230.5,405.77 231.14,405.13 235.59,405.13 236.22,404.5 238.76,404.5 240.03,405.77 242.57,405.77 A21.B2 243.21,405.77 243.84,405.13 248.28,405.13 248.92,404.5 251.46,404.5 252.73,405.77 255.27,405.77 A20.B2 255.91,405.77 256.54,405.13 260.99,405.13 261.62,404.5 264.16,404.5 265.43,405.77 267.97,405.77 A19.B2 268.61,405.77 271.78,405.77 273.05,404.5 274.95,404.5 276.86,406.4 280.67,406.4 A18.B2 281.31,405.77 284.48,405.77 285.75,404.5 287.65,404.5 289.56,406.4 293.37,406.4 A17.B2 294,405.77 294.64,405.13 299.08,405.13 299.72,404.5 302.26,404.5 303.53,405.77 306.07,405.77 A16.B2 306.7,407.04 309.88,407.04 311.15,408.31 313.06,408.31 313.69,407.67 318.13,407.67 318.77,407.04 A15.B2 319.4,405.77 322.58,405.77 323.85,404.5 325.75,404.5 327.66,406.4 331.47,406.4 A14.B2 332.11,407.04 332.74,407.67 337.19,407.67 337.82,408.31 340.36,408.31 341.63,407.04 344.17,407.04 A13.B2 344.81,407.04 347.98,407.04 349.25,408.31 351.15,408.31 351.79,407.67 356.24,407.67 356.87,407.04 A12.B2 357.5,405.77 360.68,405.77 361.95,404.5 363.86,404.5 365.76,406.4 369.57,406.4 A11.B2 370.2,405.77 370.84,405.13 375.29,405.13 375.92,404.5 378.46,404.5 379.73,405.77 382.27,405.77 A10.B2 382.9,405.77 383.54,405.13 387.99,405.13 388.62,404.5 391.16,404.5 392.43,405.77 394.97,405.77 A09.B2 395.61,405.77 396.24,405.13 400.69,405.13 401.32,404.5 403.86,404.5 405.13,405.77 407.67,405.77 A08.B2 408.31,405.77 408.94,405.13 413.38,405.13 414.02,404.5 416.56,404.5 417.83,405.77 420.37,405.77 A07.B2 421,407.04 421.64,407.67 426.08,407.67 426.72,408.31 429.26,408.31 430.53,407.04 433.07,407.04 A06.B2 433.7,405.77 434.34,405.13 438.79,405.13 439.42,404.5 441.96,404.5 443.23,405.77 445.77,405.77 A05.B2 446.4,405.77 447.04,405.13 451.49,405.13 452.12,404.5 454.66,404.5 455.93,405.77 458.47,405.77 A04.B2 459.11,405.77 462.28,405.77 463.55,404.5 465.45,404.5 466.09,405.13 470.54,405.13 471.17,405.77 A03.B2
  Bottom 0.635: C40.B2 1.91,269.24 2.54,268.61 6.99,268.61 7.62,267.97 10.16,267.97 11.43,269.24 13.97,269.24 C39.B2 14.61,269.24 15.24,268.61 19.68,268.61 20.32,267.97 22.86,267.97 24.13,269.24 26.67,269.24 C38.B2 27.3,269.24 27.94,268.61 32.38,268.61 33.02,267.97 35.56,267.97 36.83,269.24 39.37,269.24 C37.B2 40.01,269.24 43.18,269.24 44.45,267.97 46.35,267.97 48.26,269.88 52.07,269.88 C36.B2 52.7,269.24 53.34,268.61 57.78,268.61 58.42,267.97 60.96,267.97 62.23,269.24 64.77,269.24 C35.B2 65.41,269.24 68.58,269.24 69.85,267.97 71.75,267.97 72.39,268.61 76.83,268.61 77.47,269.24 C34.B2 78.11,269.24 78.74,268.61 83.19,268.61 83.82,267.97 85.09,267.97 87,269.88 90.17,269.88 C33.B2 90.81,269.24 91.44,268.61 95.89,268.61 96.52,267.97 99.06,267.97 100.33,269.24 102.87,269.24 C32.B2 103.5,269.24 104.14,268.61 108.58,268.61 109.22,267.97 111.76,267.97 113.03,269.24 115.57,269.24 C31.B2 116.2,269.24 116.84,268.61 121.28,268.61 121.92,267.97 124.46,267.97 125.73,269.24 128.27,269.24 C30.B2 128.91,269.24 132.08,269.24 133.35,267.97 135.25,267.97 135.89,268.61 140.34,268.61 140.97,269.24 C29.B2 141.6,269.24 142.24,268.61 146.69,268.61 147.32,267.97 149.86,267.97 151.13,269.24 153.67,269.24 C28.B2 154.31,270.51 157.48,270.51 158.75,271.78 160.66,271.78 161.29,271.15 165.74,271.15 166.37,270.51 C27.B2 167,269.24 167.64,268.61 172.09,268.61 172.72,267.97 173.99,267.97 175.9,269.88 179.07,269.88 C26.B2 179.71,269.24 180.34,268.61 184.78,268.61 185.42,267.97 186.69,267.97 188.59,269.88 191.77,269.88 C25.B2 192.41,269.24 195.58,269.24 196.85,267.97 198.75,267.97 200.66,269.88 204.47,269.88 C24.B2 205.1,269.24 205.74,268.61 210.19,268.61 210.82,267.97 211.46,267.97 213.36,269.88 217.17,269.88 C23.B2 217.81,269.24 222.25,269.24 223.52,267.97 226.06,267.97 227.33,269.24 229.87,269.24 C22.B2 230.5,269.24 233.68,269.24 234.95,267.97 236.85,267.97 238.76,269.88 242.57,269.88 C21.B2 243.21,269.24 246.38,269.24 247.65,267.97 249.56,267.97 251.46,269.88 255.27,269.88 C20.B2 255.91,269.24 260.35,269.24 261.62,267.97 264.16,267.97 265.43,269.24 267.97,269.24 C19.B2 268.61,269.24 271.78,269.24 273.05,267.97 274.95,267.97 276.86,269.88 280.67,269.88 C18.B2 281.31,269.24 281.94,268.61 286.38,268.61 287.02,267.97 289.56,267.97 290.83,269.24 293.37,269.24 C17.B2 294,269.24 294.64,268.61 299.08,268.61 299.72,267.97 302.26,267.97 303.53,269.24 306.07,269.24 C16.B2 306.7,269.24 307.34,268.61 311.79,268.61 312.42,267.97 314.96,267.97 316.23,269.24 318.77,269.24 C15.B2 319.4,269.24 322.58,269.24 323.85,267.97 325.75,267.97 326.39,268.61 330.83,268.61 331.47,269.24 C14.B2 332.11,269.24 335.28,269.24 336.55,267.97 338.45,267.97 339.09,268.61 343.54,268.61 344.17,269.24 C13.B2 344.81,269.88 347.98,269.88 349.88,267.97 351.15,267.97 353.06,269.88 356.87,269.88 C12.B2 357.5,270.51 361.95,270.51 363.22,271.78 365.76,271.78 367.03,270.51 369.57,270.51 C11.B2 370.2,270.51 370.84,271.15 375.29,271.15 375.92,271.78 378.46,271.78 379.73,270.51 382.27,270.51 C10.B2 382.9,269.24 383.54,268.61 387.99,268.61 388.62,267.97 391.16,267.97 392.43,269.24 394.97,269.24 C09.B2 395.61,269.24 398.78,269.24 400.05,267.97 401.95,267.97 402.59,268.61 407.04,268.61 407.67,269.24 C08.B2 408.31,269.24 408.94,268.61 413.38,268.61 414.02,267.97 416.56,267.97 417.83,269.24 420.37,269.24 C07.B2 421,269.24 424.18,269.24 425.45,267.97 427.36,267.97 427.99,268.61 432.44,268.61 433.07,269.24 C06.B2 433.7,269.24 436.88,269.24 438.15,267.97 440.06,267.97 441.96,269.88 445.77,269.88 C05.B2 446.4,269.24 447.04,268.61 451.49,268.61 452.12,267.97 454.66,267.97 455.93,269.24 458.47,269.24 C04.B2 459.11,269.24 462.28,269.24 463.55,267.97 465.45,267.97 466.09,268.61 470.54,268.61 471.17,269.24 C03.B2
  Bottom 0.635: B40.B2 1.91,335.92 2.54,335.28 6.99,335.28 7.62,334.65 v9.53,334.65 10.16,334.65 10.79,335.28 12.7,335.28 13.34,334.65 15.88,334.65 16.51,335.28 19.68,335.28 20.32,334.65 22.86,334.65 24.13,335.92 26.67,335.92 B38.B2 27.3,337.19 27.94,337.82 32.38,337.82 33.02,338.46 35.56,338.46 36.83,337.19 39.37,337.19 B37.B2 40.01,337.19 40.64,337.82 45.09,337.82 45.72,338.46 48.26,338.46 49.53,337.19 52.07,337.19 B36.B2 52.7,337.19 55.88,337.19 57.15,338.46 59.05,338.46 59.69,337.82 64.14,337.82 64.77,337.19 B35.B2 65.41,337.19 66.04,337.82 70.48,337.82 71.12,338.46 72.39,338.46 74.3,336.55 77.47,336.55 B34.B2 78.11,337.19 82.55,337.19 83.82,338.46 86.36,338.46 87.63,337.19 90.17,337.19 B33.B2 90.81,337.19 91.44,337.82 95.89,337.82 96.52,338.46 99.06,338.46 100.33,337.19 102.87,337.19 B32.B2 103.5,337.19 104.14,337.82 108.58,337.82 109.22,338.46 111.76,338.46 113.03,337.19 115.57,337.19 B31.B2 116.2,337.19 116.84,337.82 121.28,337.82 121.92,338.46 124.46,338.46 125.73,337.19 128.27,337.19 B30.B2 128.91,337.19 129.54,337.82 133.99,337.82 134.62,338.46 137.16,338.46 138.43,337.19 140.97,337.19 B29.B2 141.6,335.92 144.78,335.92 146.05,334.65 147.96,334.65 149.86,336.55 153.67,336.55 B28.B2 154.31,335.92 157.48,335.92 158.75,334.65 160.66,334.65 162.56,336.55 166.37,336.55 B27.B2 167,336.55 170.81,336.55 172.72,334.65 173.99,334.65 175.9,336.55 179.07,336.55 B26.B2 179.71,335.92 180.34,335.28 184.78,335.28 185.42,334.65 186.69,334.65 188.59,336.55 191.77,336.55 B25.B2 192.41,335.92 195.58,335.92 196.85,334.65 198.75,334.65 200.66,336.55 204.47,336.55 B24.B2 205.1,335.92 208.28,335.92 209.55,334.65 211.46,334.65 213.36,336.55 217.17,336.55 B23.B2 217.81,335.92 220.98,335.92 222.25,334.65 224.16,334.65 226.06,336.55 229.87,336.55 B22.B2 230.5,335.92 233.68,335.92 234.95,334.65 236.85,334.65 238.76,336.55 242.57,336.55 B21.B2 243.21,335.92 246.38,335.92 247.65,334.65 249.56,334.65 251.46,336.55 255.27,336.55 B20.B2 255.91,335.92 259.08,335.92 260.35,334.65 262.25,334.65 264.16,336.55 267.97,336.55 B19.B2 268.61,335.92 271.78,335.92 273.05,334.65 274.95,334.65 276.86,336.55 280.67,336.55 B18.B2 281.31,335.92 284.48,335.92 285.75,334.65 287.65,334.65 289.56,336.55 293.37,336.55 B17.B2 294,335.92 297.18,335.92 298.45,334.65 300.36,334.65 302.26,336.55 306.07,336.55 B16.B2 306.7,335.92 309.88,335.92 311.15,334.65 313.06,334.65 314.96,336.55 318.77,336.55 B15.B2 319.4,335.92 320.04,335.28 324.49,335.28 325.12,334.65 327.66,334.65 328.93,335.92 331.47,335.92 B14.B2 332.11,335.92 335.28,335.92 336.55,334.65 338.45,334.65 339.09,335.28 343.54,335.28 344.17,335.92 B13.B2 344.81,335.92 347.98,335.92 349.25,334.65 351.15,334.65 353.06,336.55 356.87,336.55 B12.B2 357.5,335.92 358.14,335.28 362.58,335.28 363.22,334.65 365.76,334.65 367.03,335.92 369.57,335.92 B11.B2 370.2,335.92 370.84,335.28 375.29,335.28 375.92,334.65 378.46,334.65 379.73,335.92 382.27,335.92 B10.B2 382.9,335.92 383.54,335.28 387.99,335.28 388.62,334.65 391.16,334.65 392.43,335.92 394.97,335.92 B09.B2 395.61,335.92 398.78,335.92 400.05,334.65 401.95,334.65 402.59,335.28 407.04,335.28 407.67,335.92 B08.B2 408.31,335.92 408.94,335.28 413.38,335.28 414.02,334.65 416.56,334.65 417.83,335.92 420.37,335.92 B07.B2 421,335.92 421.64,335.28 426.08,335.28 426.72,334.65 429.26,334.65 430.53,335.92 433.07,335.92 B06.B2 433.7,335.92 434.34,335.28 438.79,335.28 439.42,334.65 441.96,334.65 443.23,335.92 445.77,335.92 B05.B2 446.4,335.92 449.58,335.92 450.85,334.65 452.75,334.65 453.39,335.28 457.83,335.28 458.47,335.92 B04.B2 459.11,335.92 459.74,335.28 464.19,335.28 464.82,334.65 467.36,334.65 468.63,335.92 471.17,335.92 B03.B2
  Bottom 0.635: D03.B2 471.17,199.39 470.54,198.75 466.09,198.75 465.45,198.12 463.55,198.12 462.28,199.39 459.11,199.39 D04.B2 458.47,199.39 455.93,199.39 454.66,198.12 452.12,198.12 451.49,198.75 447.04,198.75 446.4,199.39 D05.B2 445.77,199.39 445.13,198.75 440.69,198.75 440.06,198.12 438.15,198.12 436.88,199.39 433.7,199.39 D06.B2 433.07,199.39 430.53,199.39 429.26,198.12 426.72,198.12 426.08,198.75 421.64,198.75 421,199.39 D07.B2 420.37,199.39 417.83,199.39 416.56,198.12 414.02,198.12 413.38,198.75 408.94,198.75 408.31,199.39 D08.B2 407.67,200.03 403.86,200.03 401.95,198.12 401.32,198.12 400.69,198.75 396.24,198.75 395.61,199.39 D09.B2 394.97,200.03 391.16,200.03 389.25,198.12 387.99,198.12 386.08,200.03 382.9,200.03 D10.B2 382.27,199.39 379.73,199.39 378.46,198.12 375.92,198.12 375.29,198.75 370.84,198.75 370.2,199.39 D11.B2 369.57,199.39 368.94,198.75 364.49,198.75 363.86,198.12 361.95,198.12 360.68,199.39 357.5,199.39 D12.B2 356.87,199.39 354.33,199.39 353.06,198.12 350.52,198.12 349.88,198.75 345.44,198.75 344.81,199.39 D13.B2 344.17,199.39 341.63,199.39 340.36,198.12 337.82,198.12 337.19,198.75 332.74,198.75 332.11,199.39 D14.B2 331.47,199.39 328.93,199.39 327.66,198.12 325.12,198.12 324.49,198.75 320.04,198.75 319.4,199.39 D15.B2 318.77,200.03 314.96,200.03 313.06,198.12 311.15,198.12 309.88,199.39 306.7,199.39 D16.B2 306.07,199.39 305.44,198.75 300.99,198.75 300.36,198.12 298.45,198.12 297.18,199.39 294,199.39 D17.B2 293.37,199.39 290.83,199.39 289.56,198.12 287.02,198.12 286.38,198.75 281.94,198.75 281.31,199.39 D18.B2 280.67,200.03 276.86,200.03 274.95,198.12 273.05,198.12 271.78,199.39 268.61,199.39 D19.B2 267.97,200.66 265.43,200.66 264.16,201.93 261.62,201.93 260.99,201.29 256.54,201.29 255.91,200.66 D20.B2 255.27,199.39 252.73,199.39 251.46,198.12 248.92,198.12 248.28,198.75 243.84,198.75 243.21,199.39 D21.B2 242.57,199.39 240.03,199.39 238.76,198.12 236.22,198.12 235.59,198.75 231.14,198.75 230.5,199.39 D22.B2 229.87,200.03 226.69,200.03 224.79,198.12 223.52,198.12 222.88,198.75 218.44,198.75 217.81,199.39 D23.B2 217.17,200.03 213.36,200.03 211.46,198.12 209.55,198.12 208.28,199.39 205.1,199.39 D24.B2 204.47,200.03 200.66,200.03 198.75,198.12 196.85,198.12 195.58,199.39 192.41,199.39 D25.B2 191.77,200.03 187.96,200.03 186.06,198.12 184.15,198.12 182.88,199.39 179.71,199.39 D26.B2 179.07,200.03 175.26,200.03 173.35,198.12 171.45,198.12 170.18,199.39 167,199.39 D27.B2 166.37,200.66 165.74,201.29 161.29,201.29 160.66,201.93 158.75,201.93 157.48,200.66 154.31,200.66 D28.B2 153.67,199.39 151.13,199.39 149.86,198.12 147.32,198.12 146.69,198.75 142.24,198.75 141.6,199.39 D29.B2 140.97,199.39 138.43,199.39 137.16,198.12 134.62,198.12 133.99,198.75 129.54,198.75 128.91,199.39 D30.B2 128.27,199.39 125.73,199.39 124.46,198.12 121.92,198.12 121.28,198.75 116.84,198.75 116.2,199.39 D31.B2 115.57,199.39 113.03,199.39 111.76,198.12 109.22,198.12 108.58,198.75 104.14,198.75 103.5,199.39 D32.B2 102.87,199.39 100.33,199.39 99.06,198.12 96.52,198.12 95.89,198.75 91.44,198.75 90.81,199.39 D33.B2 90.17,199.39 87.63,199.39 86.36,198.12 83.82,198.12 83.19,198.75 78.74,198.75 78.11,199.39 D34.B2 77.47,199.39 74.93,199.39 73.66,198.12 71.12,198.12 70.48,198.75 66.04,198.75 65.41,199.39 D35.B2 64.77,199.39 62.23,199.39 60.96,198.12 58.42,198.12 57.78,198.75 53.34,198.75 52.7,199.39 D36.B2 52.07,199.39 49.53,199.39 48.26,198.12 45.72,198.12 45.09,198.75 40.64,198.75 40.01,199.39 D37.B2 39.37,200.66 36.83,200.66 35.56,201.93 33.02,201.93 32.38,201.29 27.94,201.29 27.3,200.66 D38.B2 26.67,200.66 24.13,200.66 22.86,201.93 20.32,201.93 19.68,201.29 15.24,201.29 14.61,200.66 D39.B2 13.97,200.03 v9.53,200.03
  Bottom 0.635: E36.B2 52.7,133.99 53.34,134.62 57.78,134.62 58.42,135.25 60.96,135.25 62.23,133.99 64.77,133.99 E35.B2 65.41,133.99 66.04,134.62 70.48,134.62 71.12,135.25 73.66,135.25 74.93,133.99 77.47,133.99 E34.B2 78.11,133.99 78.74,134.62 83.19,134.62 83.82,135.25 86.36,135.25 87.63,133.99 90.17,133.99 E33.B2 90.81,133.99 91.44,134.62 95.89,134.62 99.69,138.43 | 142.24,134.62 141.6,133.99 E29.B2 | 142.24,134.62 146.69,134.62 147.32,135.25 149.86,135.25 151.13,133.99 153.67,133.99 E28.B2 154.31,132.72 157.48,132.72 158.75,131.44 160.66,131.44 161.29,132.08 165.74,132.08 166.37,132.72 E27.B2 167,132.72 170.18,132.72 171.45,131.44 173.35,131.44 175.26,133.35 179.07,133.35 E26.B2 179.71,132.72 182.88,132.72 184.15,131.44 186.06,131.44 187.96,133.35 191.77,133.35 E25.B2 192.41,132.72 195.58,132.72 196.85,131.44 198.75,131.44 200.66,133.35 204.47,133.35 E24.B2 205.1,132.72 209.55,132.72 210.82,131.44 212.09,131.44 214,133.35 217.17,133.35 E23.B2 217.81,132.72 218.44,132.08 222.88,132.08 223.52,131.44 224.79,131.44 226.69,133.35 229.87,133.35 E22.B2 230.5,132.72 233.68,132.72 234.95,131.44 236.85,131.44 238.76,133.35 242.57,133.35 E21.B2 243.21,132.72 246.38,132.72 247.65,131.44 249.56,131.44 251.46,133.35 255.27,133.35 E20.B2 255.91,132.72 259.08,132.72 260.35,131.44 262.25,131.44 264.16,133.35 267.97,133.35 E19.B2 268.61,132.72 271.78,132.72 273.05,131.44 274.95,131.44 276.86,133.35 280.67,133.35 E18.B2 281.31,132.72 284.48,132.72 285.75,131.44 287.65,131.44 289.56,133.35 293.37,133.35 E17.B2 294,132.72 297.18,132.72 298.45,131.44 300.36,131.44 302.26,133.35 306.07,133.35 E16.B2 306.7,132.72 309.88,132.72 311.15,131.44 313.06,131.44 314.96,133.35 318.77,133.35 E15.B2 319.4,133.99 323.85,133.99 325.12,135.25 327.66,135.25 328.93,133.99 331.47,133.99 E14.B2 332.11,132.72 335.28,132.72 336.55,131.44 338.45,131.44 340.36,133.35 344.17,133.35 E13.B2 344.81,132.72 347.98,132.72 349.25,131.44 351.15,131.44 353.06,133.35 356.87,133.35 E12.B2 357.5,132.72 360.68,132.72 361.95,131.44 363.86,131.44 365.76,133.35 369.57,133.35 E11.B2 370.2,132.72 373.38,132.72 374.65,131.44 376.56,131.44 378.46,133.35 382.27,133.35 E10.B2 382.9,133.35 385.44,133.35 387.35,131.44 389.25,131.44 391.16,133.35 394.97,133.35 E09.B2 395.61,132.72 396.24,132.08 400.69,132.08 401.32,131.44 403.86,131.44 405.13,132.72 407.67,132.72 E08.B2 408.31,132.72 411.48,132.72 412.75,131.44 414.65,131.44 416.56,133.35 420.37,133.35 E07.B2 421,132.72 424.18,132.72 425.45,131.44 427.36,131.44 429.26,133.35 433.07,133.35 E06.B2 433.7,132.72 436.88,132.72 438.15,131.44 440.06,131.44 441.96,133.35 445.77,133.35 E05.B2 446.4,133.35 450.21,133.35 452.12,131.44 452.75,131.44 454.66,133.35 458.47,133.35 E04.B2 459.11,132.72 459.74,132.08 464.19,132.08 464.82,131.44 467.36,131.44 468.63,132.72 471.17,132.72 E03.B2
  Bottom 0.635: 99.69,138.43 138.43,138.43 142.24,134.62 | F40.B2 1.91,64.13 2.54,64.77 6.99,64.77 7.62,65.41 10.16,65.41 11.43,64.13 13.97,64.13 F39.B2 14.61,64.13 15.24,64.77 19.68,64.77 20.32,65.41 22.86,65.41 24.13,64.13 26.67,64.13 F38.B2 27.3,64.13 27.94,64.77 32.38,64.77 33.02,65.41 35.56,65.41 36.83,64.13 39.37,64.13 F37.B2 40.01,64.13 40.64,64.77 45.09,64.77 45.72,65.41 48.26,65.41 49.53,64.13 52.07,64.13 F36.B2 52.7,64.13 53.34,64.77 57.78,64.77 58.42,65.41 60.96,65.41 62.23,64.13 64.77,64.13 F35.B2 65.41,64.13 66.04,64.77 70.48,64.77 71.12,65.41 73.66,65.41 74.93,64.13 77.47,64.13 F34.B2 78.11,62.87 78.74,62.23 83.19,62.23 83.82,61.59 86.36,61.59 87.63,62.87 90.17,62.87 F33.B2 90.81,64.13 91.44,64.77 95.89,64.77 100.33,69.22 v136.53,69.22 150.5,69.22 154.94,64.77 | 154.94,64.77 154.31,64.13 F28.B2 | 154.94,64.77 159.38,64.77 160.02,65.41 162.56,65.41 163.83,64.13 166.37,64.13 F27.B2 167,64.13 170.18,64.13 171.45,65.41 173.35,65.41 173.99,64.77 178.44,64.77 179.07,64.13 F26.B2 179.71,62.87 184.15,62.87 185.42,61.59 186.69,61.59 188.59,63.5 191.77,63.5 F25.B2 192.41,62.87 193.04,62.23 197.49,62.23 198.12,61.59 200.66,61.59 201.93,62.87 204.47,62.87 F24.B2 205.1,62.87 205.74,62.23 210.19,62.23 210.82,61.59 213.36,61.59 214.63,62.87 217.17,62.87 F23.B2 217.81,62.87 218.44,62.23 222.88,62.23 223.52,61.59 226.06,61.59 227.33,62.87 229.87,62.87 F22.B2 230.5,62.87 231.14,62.23 235.59,62.23 236.22,61.59 238.76,61.59 240.03,62.87 242.57,62.87 F21.B2 243.21,62.87 243.84,62.23 248.28,62.23 248.92,61.59 251.46,61.59 252.73,62.87 255.27,62.87 F20.B2 255.91,62.87 256.54,62.23 260.99,62.23 261.62,61.59 264.16,61.59 265.43,62.87 267.97,62.87 F19.B2 268.61,64.13 273.05,64.13 274.32,65.41 276.86,65.41 278.13,64.13 280.67,64.13 F18.B2 281.31,62.87 284.48,62.87 285.75,61.59 287.65,61.59 289.56,63.5 293.37,63.5 F17.B2 294,62.87 297.18,62.87 298.45,61.59 300.36,61.59 302.26,63.5 306.07,63.5 F16.B2 306.7,62.87 311.15,62.87 312.42,61.59 313.06,61.59 314.96,63.5 318.77,63.5 F15.B2 319.4,62.87 320.04,62.23 324.49,62.23 325.12,61.59 327.66,61.59 328.93,62.87 331.47,62.87 F14.B2 332.11,62.87 332.74,62.23 337.19,62.23 337.82,61.59 340.36,61.59 341.63,62.87 344.17,62.87 F13.B2 344.81,64.13 345.44,64.77 349.88,64.77 350.52,65.41 353.06,65.41 354.33,64.13 356.87,64.13 F12.B2 357.5,64.13 358.14,64.77 362.58,64.77 363.22,65.41 365.76,65.41 367.03,64.13 369.57,64.13 F11.B2 370.2,62.87 370.84,62.23 375.29,62.23 375.92,61.59 378.46,61.59 379.73,62.87 382.27,62.87 F10.B2 382.9,62.87 383.54,62.23 387.99,62.23 388.62,61.59 391.16,61.59 392.43,62.87 394.97,62.87 F09.B2 395.61,64.13 396.24,64.77 400.69,64.77 401.32,65.41 403.86,65.41 405.13,64.13 407.67,64.13 F08.B2 408.31,64.13 411.48,64.13 412.75,65.41 414.65,65.41 415.29,64.77 419.74,64.77 420.37,64.13 F07.B2 421,64.13 421.64,64.77 426.08,64.77 426.72,65.41 429.26,65.41 430.53,64.13 433.07,64.13 F06.B2 433.7,62.87 434.34,62.23 438.79,62.23 439.42,61.59 441.96,61.59 443.23,62.87 445.77,62.87 F05.B2 446.4,62.87 447.04,62.23 451.49,62.23 452.12,61.59 454.66,61.59 455.93,62.87 458.47,62.87 F04.B2 459.11,62.87 462.28,62.87 463.55,61.59 465.45,61.59 466.09,62.23 470.54,62.23 471.17,62.87 F03.B2
  Bottom 0.635: v98.42,139.06 99.06,138.43 99.69,138.43
-(DP+EP)  (via drill 0.61)
  Top 0.254: v290.19,290.83 288.93,289.56 v288.93,282.58 | v334.64,281.31 334.64,288.29 B14.U2 | v317.5,374.02 v317.5,360.05 | v279.4,323.22 279.4,294 280.67,292.74 B18.T2 | v257.81,325.75 257.18,326.39 v257.18,370.84
  Route2 0.254: v113.03,375.92 113.67,376.56 124.46,376.56 128.27,372.75 135.25,372.75 138.43,375.92 144.15,375.92 147.32,372.75 149.86,372.75 150.5,373.38 155.57,373.38 156.84,372.11 A28.P2 | v317.5,374.02 316.87,373.38 313.69,373.38 313.06,372.75 306.7,372.75 303.53,369.57 300.99,369.57 297.81,372.75 291.46,372.75 290.83,373.38 288.29,373.38 285.12,370.21 v280.67,370.21
  Bottom 0.254: v290.19,290.83 289.56,290.2 282.57,290.2 281.31,291.47 B18.T2 | v288.93,282.58 289.56,283.21 317.5,283.21 319.4,281.31 320.04,281.31 320.68,281.94 334.01,281.94 v334.64,281.31 | 257.18,372.75 264.16,372.75 264.8,373.38 269.88,373.38 271.14,372.11 A19.P2 271.78,370.84 274.32,370.84 275.59,369.57 280.04,369.57 v280.67,370.21 | 257.18,372.75 254,372.75 250.19,376.56 242.57,376.56 238.76,372.75 233.04,372.75 232.41,373.38 226.69,373.38 222.88,369.57 214,369.57 210.19,373.38 201.29,373.38 200.66,372.75 198.12,372.75 197.49,373.38 188.59,373.38 187.96,372.75 185.42,372.75 184.78,373.38 175.9,373.38 175.26,372.75 165.1,372.75 164.47,373.38 163.19,373.38 161.93,372.11 157.48,372.11 A28.P2 | v113.03,375.92 112.39,375.92 111.76,376.56 104.14,376.56 100.97,379.73 99.69,379.73 99.06,379.1 92.71,379.1 83.19,369.57 74.3,369.57 70.48,373.38 61.59,373.38 60.96,372.75 53.98,372.75 52.7,374.02 A36.N2 | v317.5,360.05 325.75,360.05 326.39,360.68 328.93,360.68 329.56,360.05 338.45,360.05 339.09,360.68 346.07,360.68 347.35,359.41 A13.U2 | v279.4,323.22 276.86,325.75 266.06,325.75 265.43,325.12 262.89,325.12 262.25,325.75 v257.81,325.75 | 257.18,372.75 v257.18,370.84
-(EX+DC)  (via drill 0.61)
  Top 0.254: v61.59,233.04 63.5,233.04 v63.5,273.05 | v88.9,274.96 88.27,275.59 88.27,287.66 88.9,288.29 88.9,328.3 90.17,329.56 B33.D2 | v372.11,261.62 371.48,262.25 371.48,278.77 372.75,280.04 372.75,283.85 372.11,284.48 372.11,285.12 v372.75,285.75 | v338.45,319.41 335.92,321.95 335.92,323.85 332.11,327.66 332.11,329.56 B14.D2
  Route3 0.254: B14.D2 332.11,330.84 332.11,334.65 333.38,335.92 333.38,344.81 336.55,347.98 336.55,363.86 337.82,365.12 337.82,366.4 336.55,367.67 336.55,389.25 344.17,396.88 344.17,399.42 A13.D2 | v347.98,292.74 342.9,297.81 342.9,314.96 v338.45,319.41
  Bottom 0.254: v61.59,233.04 60.96,233.68 52.07,233.68 48.26,229.87 45.72,229.87 45.09,230.5 36.2,230.5 35.56,229.87 28.57,229.87 27.3,231.14 C38.R2 | v63.5,273.05 65.41,274.96 v88.9,274.96 | v372.11,261.62 376.56,261.62 377.19,262.25 379.73,262.25 380.37,261.62 389.25,261.62 389.89,262.25 392.43,262.25 393.06,261.62 401.95,261.62 402.59,262.25 405.13,262.25 407.04,260.35 410.85,260.35 C08.E2 | v372.75,285.75 371.48,287.02 364.49,287.02 363.86,287.66 354.96,287.66 354.33,287.02 353.69,287.02 v347.98,292.74 | B33.D2 90.81,330.2 94.61,330.2 96.52,332.11 99.06,332.11 99.69,331.47 108.58,331.47 109.22,332.11 111.76,332.11 112.39,331.47 121.28,331.47 121.92,332.11 124.46,332.11 125.09,331.47 133.99,331.47 134.62,332.11 137.16,332.11 137.79,331.47 146.69,331.47 147.32,332.11 149.86,332.11 150.5,331.47 159.38,331.47 160.02,332.11 162.56,332.11 163.19,331.47 172.09,331.47 172.72,332.11 175.26,332.11 175.9,331.47 176.53,331.47 177.16,332.11 187.96,332.11 188.59,331.47 197.49,331.47 198.12,332.11 200.66,332.11 201.29,331.47 210.19,331.47 210.82,332.11 213.36,332.11 214,331.47 222.88,331.47 223.52,332.11 226.06,332.11 226.69,331.47 235.59,331.47 236.22,332.11 238.76,332.11 239.4,331.47 248.28,331.47 248.92,332.11 251.46,332.11 252.09,331.47 260.99,331.47 261.62,332.11 264.16,332.11 264.8,331.47 273.69,331.47 274.32,332.11 276.86,332.11 277.5,331.47 286.38,331.47 287.02,332.11 289.56,332.11 290.19,331.47 299.08,331.47 299.72,332.11 302.26,332.11 302.89,331.47 311.79,331.47 312.42,332.11 314.96,332.11 315.6,331.47 324.49,331.47 325.12,332.11 326.39,332.11 328.3,330.2 331.47,330.2 B14.D2
-(IAC+CMA)  (via drill 0.61)
  Top 0.254: v190.5,205.1 v190.5,247.01 | v233.68,148.59 233.04,147.95 v233.04,142.24
  Route2 0.254: v233.68,250.82 231.78,252.73 227.97,252.73 227.33,252.09 224.79,252.09 221.62,255.27 219.07,255.27 v214.63,250.82 | v220.34,19.05 222.25,17.14 226.06,17.14 226.69,17.78 232.41,17.78 233.68,19.05 234.31,19.05 v236.22,17.14 | v372.75,120.02 370.84,121.92 364.49,121.92 363.86,122.55 363.22,122.55 361.95,121.28 361.95,118.74 358.14,118.74 v357.5,118.11 | v360.05,144.78 359.41,144.14 353.06,144.14 351.79,145.41 294.64,145.41 292.1,142.88 265.43,142.88 263.52,144.78 237.49,144.78 v233.68,148.59 | v233.04,142.24 231.78,140.97 222.25,140.97 217.81,145.41 205.1,145.41 201.29,141.6 193.68,141.6 v188.59,146.69
  Route3 0.254: v248.92,320.68 248.28,320.04 248.28,318.77 247.65,318.14 247.65,313.69 244.47,310.52 244.47,303.53 241.3,300.36 241.3,276.86 238.12,273.69 238.12,258.44 239.4,257.18 235.59,253.36 235.59,252.73 v233.68,250.82 | v190.5,205.1 190.5,201.93 189.87,201.29 189.87,198.12 190.5,197.48 190.5,151.76 188.59,149.86 v188.59,146.69 188.59,138.43 187.32,137.16 187.32,77.47 192.41,72.39 192.41,65.41 193.68,64.13 193.68,45.72 v220.34,19.05 | v376.56,103.5 374.65,105.41 374.65,118.11 v372.75,120.02 | v357.5,118.11 358.77,119.38 358.77,143.51 v360.05,144.78
  Bottom 0.254: v248.92,320.68 246.38,320.68 B21.H2 | v214.63,250.82 214,250.19 212.72,250.19 211.46,248.92 202.56,248.92 201.93,249.56 201.29,249.56 198.75,247.01 196.85,247.01 196.22,246.38 191.13,246.38 v190.5,247.01 | v236.22,17.14 238.76,17.14 239.4,17.78 248.28,17.78 248.92,17.14 251.46,17.14 252.09,17.78 260.99,17.78 261.62,17.14 262.89,17.14 264.16,18.41 267.97,18.41 F19.T2 | v376.56,103.5 377.19,102.87 387.35,102.87 387.35,97.79 386.71,97.16 384.18,97.16 382.9,95.88 E10.R2
-(ISZ*Z1)  (via drill 0.61)
  Top 0.254: v369.57,75.56 369.57,81.91 E11.V2
  Route3 0.254: v306.7,34.92 306.7,32.38 F16.N2 | v361.95,38.73 365.12,41.91 365.12,52.7 361.95,55.88 361.95,69.85 360.05,71.75 v360.05,75.56
  Bottom 0.254: v306.7,34.92 307.98,36.2 314.96,36.2 315.6,36.83 324.49,36.83 325.12,36.2 327.66,36.2 328.3,36.83 337.19,36.83 341,33.02 343.54,33.02 346.71,36.2 353.06,36.2 353.69,36.83 360.05,36.83 v361.95,38.73 | v360.05,75.56 v369.57,75.56
-(JMP+JMS)(B)  (via drill 0.61)
  Top 0.254: v123.83,98.42 123.83,29.21 119.38,29.21 F31.P2
  Bottom 0.254: v123.83,98.42 123.83,100.33 133.99,100.33 134.62,99.69 137.16,99.69 138.43,100.96 140.97,100.96 E29.N2
-(OP+IOT)  (via drill 0.61)
  Top 0.254: v304.8,355.6 v304.8,389.25 | v346.07,31.12 345.44,30.48 345.44,26.67 344.81,26.03 F13.R2 | v358.14,33.02 358.77,33.66 v358.77,50.8 | v423.55,163.19 422.27,164.47 422.27,165.73 423.55,167 423.55,170.81 D07.M2
  Route2 0.254: v300.36,287.66 303.53,284.48 311.79,284.48 312.42,283.85 327.02,283.85 v328.93,285.75 | v389.25,163.83 389.89,163.19 v396.88,163.19
  Route3 0.254: 298.45,294 295.27,294 294,295.28 294,297.81 B17.R2 | 298.45,294 298.45,339.73 304.8,346.08 v304.8,355.6 | v358.77,50.8 358.77,99.69 v360.68,101.6 | v410.21,172.72 409.57,172.09 409.57,147.95 404.5,142.88 404.5,138.43 403.23,137.16 403.23,109.22 v404.5,107.95 | 298.45,294 298.45,289.56 v300.36,287.66 | v328.93,285.75 335.28,279.4 335.28,274.96 336.55,273.69 v336.55,254.63 | v341,251.46 342.9,249.56 342.9,236.85 347.35,232.41 347.35,230.5 346.07,229.23 346.07,211.45 349.25,208.28 349.25,184.78 352.43,181.61 352.43,176.53 v354.33,174.62
  Bottom 0.254: v304.8,389.25 307.34,391.8 314.96,391.8 319.4,396.24 321.94,396.24 A15.E2 | v346.07,31.12 348.62,33.66 353.06,33.66 353.69,33.02 v358.14,33.02 | v360.68,101.6 362.58,103.5 365.76,103.5 366.39,102.87 371.48,102.87 372.75,104.14 E11.M2 373.38,105.41 377.19,105.41 378.46,106.68 379.73,106.68 380.37,106.04 389.25,106.04 389.89,106.68 392.43,106.68 393.06,106.04 402.59,106.04 v404.5,107.95 | v410.21,172.72 414.65,172.72 415.29,173.35 417.83,173.35 419.74,171.45 423.55,171.45 D07.M2 | v336.55,254.63 339.73,251.46 v341,251.46 | v354.33,174.62 356.24,172.72 364.49,172.72 365.76,173.99 368.3,173.99 369.57,172.72 375.92,172.72 384.81,163.83 v389.25,163.83 | v396.88,163.19 397.51,163.83 403.86,163.83 404.5,163.19 413.38,163.19 414.02,163.83 416.56,163.83 417.19,163.19 v423.55,163.19
-(SP+PCP)  (via drill 0.61)
  Top 0.254: v433.07,52.7 431.8,53.98 431.8,69.22 v426.72,74.29 | v384.18,76.83 384.18,112.39 385.44,113.66 385.44,116.84 E10.H2 | v161.93,285.75 v161.93,298.45 | v156.21,302.9 155.57,303.53 155.57,320.68 154.31,321.95 154.31,323.22 B28.F2 | A19.V2 268.61,356.24 269.88,357.5 v269.88,378.46 269.88,382.27 268.61,383.54 268.61,386.72 A19.J2 | v274.32,28.58 273.05,29.84 273.05,52.07 271.78,53.34 F19.E2 271.78,54.61 273.05,55.88 273.05,97.16 | B22.R2 229.87,297.81 228.6,296.55 v228.6,277.5 229.24,276.86 229.24,275.59 v229.87,274.96 | B19.M2 271.78,307.34 273.05,306.07 273.05,288.29 272.42,287.66 272.42,278.13 v271.78,277.5 273.05,276.23 273.05,97.16 | v167,272.42 167.64,273.05 167.64,284.48 167,285.12 B27.V2 | 273.05,97.16 v274.95,97.16
  Route2 0.254: v161.93,285.75 166.37,285.75 B27.V2 | v184.15,270.51 185.42,271.78 187.96,271.78 191.77,267.97 199.39,267.97 206.38,274.96 v229.87,274.96 | v325.75,99.69 327.66,101.6 328.3,101.6 332.74,97.16 338.45,97.16 339.09,96.52 349.88,96.52 353.69,100.33 354.33,100.33 354.96,99.69 363.86,99.69 364.49,100.33 372.11,100.33 381,109.22 381.63,109.22 381.63,111.12 382.9,112.39 385.44,112.39 385.44,116.84 E10.H2
  Route3 0.254: v274.32,28.58 280.04,22.86 283.85,22.86 F18.S2 | A19.V2 268.61,354.97 268.61,347.98 269.88,346.71 269.88,311.79 271.14,310.52 271.14,308.61 B19.M2
  Bottom 0.254: v433.07,52.7 440.06,52.7 441.32,51.44 445.77,51.44 F05.F2 | v426.72,74.29 426.08,74.93 405.13,74.93 404.5,75.56 385.44,75.56 v384.18,76.83 | v161.93,298.45 161.93,302.9 v156.21,302.9 | B34.F2 78.11,324.49 79.38,325.75 86.36,325.75 87,325.12 95.89,325.12 96.52,325.75 99.06,325.75 102.87,321.95 111.76,321.95 115.57,325.75 124.46,325.75 125.09,325.12 133.99,325.12 134.62,325.75 137.16,325.75 137.79,325.12 146.69,325.12 147.32,325.75 148.59,325.75 149.86,324.49 153.67,324.49 B28.F2 | v269.88,378.46 270.51,379.1 274.95,379.1 275.59,379.73 278.13,379.73 278.76,379.1 287.65,379.1 288.29,379.73 295.27,379.73 296.55,378.46 A17.M2 | v228.6,277.5 229.24,278.13 271.14,278.13 v271.78,277.5 | v167,272.42 167.64,271.78 175.26,271.78 175.9,271.15 180.97,271.15 181.61,270.51 v184.15,270.51 | v325.75,99.69 316.87,99.69 316.23,100.33 313.69,100.33 313.06,99.69 304.17,99.69 303.53,100.33 300.99,100.33 300.36,99.69 291.46,99.69 290.83,100.33 288.29,100.33 284.48,96.52 275.59,96.52 v274.95,97.16
-(SP+PCP+LP)  (via drill 0.61)
  Top 0.254: B11.F2 370.2,323.22 370.2,319.41 371.48,318.14 371.48,300.36 370.2,299.09 B11.R2 | v48.9,238.12 50.8,240.03 v50.8,278.13 | v231.14,276.23 231.78,276.86 231.78,287.66 230.5,288.93 230.5,291.47 B22.T2
  Route2 0.254: v309.25,292.74 310.51,294 313.06,294 313.69,293.37 318.77,293.37 319.4,294 325.75,294 327.66,292.1 328.3,292.1 330.2,294 338.45,294 339.09,293.37 341.63,293.37 342.26,294 348.62,294 353.06,298.45 356.87,298.45 B12.R2 | v252.09,287.02 245.75,293.37 237.49,293.37 236.85,294 231.78,294 230.5,292.74 B22.T2
  Bottom 0.254: B11.F2 370.2,323.22 371.48,321.95 378.46,321.95 379.73,323.22 382.27,323.22 B10.F2 | B12.R2 357.5,298.45 361.31,298.45 363.22,300.36 364.49,300.36 366.39,298.45 369.57,298.45 B11.R2 370.2,299.09 371.48,300.36 376.56,300.36 378.46,298.45 382.27,298.45 B10.R2 | v48.9,238.12 46.99,236.22 43.81,236.22 43.18,235.59 C37.P2 | v50.8,278.13 51.44,278.77 74.93,278.77 75.56,279.4 144.78,279.4 146.05,278.13 160.66,278.13 162.56,280.04 196.85,280.04 198.12,278.77 205.74,278.77 208.28,276.23 v231.14,276.23 | v309.25,292.74 307.34,290.83 302.26,290.83 298.45,287.02 292.1,287.02 287.02,281.94 267.97,281.94 266.06,283.85 255.27,283.85 v252.09,287.02
-(WTX*IAC)  (via drill 0.61)
  Top 0.254: v419.1,305.44 419.1,300.36 418.46,299.72 418.46,296.55 419.1,295.91 419.1,277.5 v420.37,276.23 | v465.45,212.09 464.82,211.45 v464.82,203.84 | v360.68,200.66 361.95,201.93 361.95,205.74 357.5,210.19 357.5,218.44 C12.V2
  Route2 0.254: v382.9,340.36 384.81,338.46 389.89,338.46 396.24,332.11 403.23,332.11 419.1,316.23 v419.1,305.44 | v420.37,276.23 421.64,274.96 432.44,274.96 448.31,259.08 452.75,259.08 457.2,254.63 457.2,250.82 455.93,249.56 457.2,248.28 460.38,248.28 461.01,248.92 464.82,248.92 482.6,231.14 482.6,216.53 471.17,216.53 466.73,212.09 v465.45,212.09 | v464.82,203.84 462.28,201.29 453.39,201.29 452.75,201.93 443.87,201.93 436.88,194.94 427.99,194.94 427.36,195.58 419.74,195.58 415.93,191.77 406.4,191.77 396.88,201.29 390.52,201.29 388.62,203.2 387.99,203.2 383.54,198.75 377.19,198.75 376.56,198.12 367.67,198.12 367.03,198.75 364.49,198.75 363.86,198.12 363.22,198.12 v360.68,200.66
  Route3 0.254: v382.9,340.36 378.46,344.81 378.46,351.16 349.25,380.37 344.81,380.37 A13.L2
  Bottom 0.254: C12.V2 357.5,219.71 359.41,221.61 360.05,221.61 C12.U2
-(WTX*ISZ)  (via drill 0.61)
  Top 0.254: v341,374.02 342.9,375.92 342.9,385.45 344.17,386.72 A13.J2 344.17,387.99 344.17,391.16 v343.54,391.8 | v405.76,230.5 405.76,233.68 406.4,234.31 v406.4,298.45 406.4,309.25 v404.5,311.15 | v388.62,371.48 390.52,369.57 390.52,325.12 v393.7,321.95
  Route2 0.254: v393.7,321.95 v404.5,311.15
  Route3 0.254: v306.7,370.84 306.7,368.94 A16.R2
  Bottom 0.254: v306.7,370.84 308.61,372.75 314.96,372.75 315.6,373.38 316.87,373.38 317.5,372.75 327.66,372.75 328.3,373.38 337.19,373.38 337.82,372.75 339.73,372.75 v341,374.02 342.26,372.75 353.06,372.75 353.69,373.38 362.58,373.38 363.22,372.75 365.76,372.75 366.39,373.38 368.94,373.38 372.11,370.21 374.65,370.21 377.82,373.38 386.71,373.38 v388.62,371.48 | v343.54,391.8 351.15,391.8 351.79,392.43 354.33,392.43 354.96,391.8 363.86,391.8 364.49,392.43 367.03,392.43 367.67,391.8 376.56,391.8 377.82,393.06 382.27,393.06 A10.F2 | v405.76,230.5 404.5,230.5 403.86,229.87 401.32,229.87 400.69,230.5 391.8,230.5 391.16,229.87 381,229.87 380.37,230.5 379.1,230.5 378.46,229.87 371.48,229.87 370.2,231.14 C11.R2 | v406.4,298.45 406.4,300.99 410.85,300.99 B08.P2
-(WTX*JMS)  (via drill 0.61)
  Top 0.254: v388.62,228.6 390.52,230.5 390.52,275.59 387.35,278.77 v387.35,279.4 | v384.81,280.04 381,283.85 381,372.75 | 381,372.75 382.27,374.02 A10.N2 | v384.81,395.61 381,395.61 381,372.75
  Route2 0.254: v388.62,228.6 386.08,228.6 C10.S2 | v387.35,279.4 386.71,280.04 v384.81,280.04
  Bottom 0.254: v384.81,395.61 389.25,395.61 389.89,394.97 396.88,394.97 398.14,396.24 A09.E2
-(WTX*OP2)  (via drill 0.61)
  Top 0.254: v285.12,381 288.93,377.19 288.93,369.57 v290.19,368.3 | v306.07,365.76 305.44,365.12 305.44,363.22 306.07,362.59 A16.T2 | v318.77,294.64 320.04,295.91 320.04,297.18 320.68,297.81 320.68,308.61 323.21,311.15 320.68,313.69 320.68,314.96 321.94,316.23 v321.94,316.87 | v408.31,190.5 409.57,191.77 409.57,206.38 408.94,207.01 414.02,212.09 v415.93,212.09 | v474.98,278.77 473.07,280.67 473.07,292.74 469.9,295.91 v469.9,323.85
  Route2 0.254: v285.12,381 284.48,381.64 284.48,383.54 A18.K2 | v408.31,190.5 405.13,187.32 404.5,187.32 402.59,189.23 399.42,189.23 398.78,189.86 D09.E2 | v415.93,212.09 419.1,212.09 421,214 447.04,214 448.31,212.72 451.49,212.72 453.39,210.82 478.15,210.82 488.95,221.61 488.95,252.73 486.41,252.73 v477.52,261.62 | v469.9,323.85 468.63,325.12 468,325.12 451.49,341.63 438.15,341.63 434.34,345.44 404.5,345.44 402.59,347.35 377.19,347.35 374.01,350.52 351.79,350.52 349.25,353.06 317.5,353.06 309.25,361.31 306.7,361.31 A16.T2
  Route3 0.254: v318.77,294.64 317.5,293.37 317.5,287.66 318.77,286.39 B15.V2 | v306.7,320.68 304.8,322.58 304.8,339.09 309.88,344.17 309.88,356.24 306.7,359.41 306.7,361.31 A16.T2 | v477.52,261.62 476.25,262.89 476.25,277.5 v474.98,278.77
  Bottom 0.254: v290.19,368.3 290.83,367.67 292.1,367.67 293.37,366.4 302.26,366.4 302.89,367.03 304.8,367.03 v306.07,365.76 | v321.94,316.87 320.04,318.77 313.69,318.77 313.06,319.41 307.98,319.41 v306.7,320.68
-(WTX*ROTR)  (via drill 0.61)
  Top 0.254: v169.54,325.12 171.45,325.12 171.45,346.08 173.35,347.98 v173.35,353.7 | v297.18,406.4 293.37,410.21 v293.37,412.12 | v190.5,413.39 190.5,389.89 189.23,388.62 v189.23,387.99
  Route2 0.254: v169.54,325.12 167.64,325.12 167,324.49 B27.F2
  Route3 0.254: v297.18,406.4 304.8,398.78 304.8,395.61 306.07,394.34 A16.F2 | v189.23,387.99 184.15,382.91 184.15,370.21 180.97,367.03 180.97,357.5 179.71,356.24 A26.V2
